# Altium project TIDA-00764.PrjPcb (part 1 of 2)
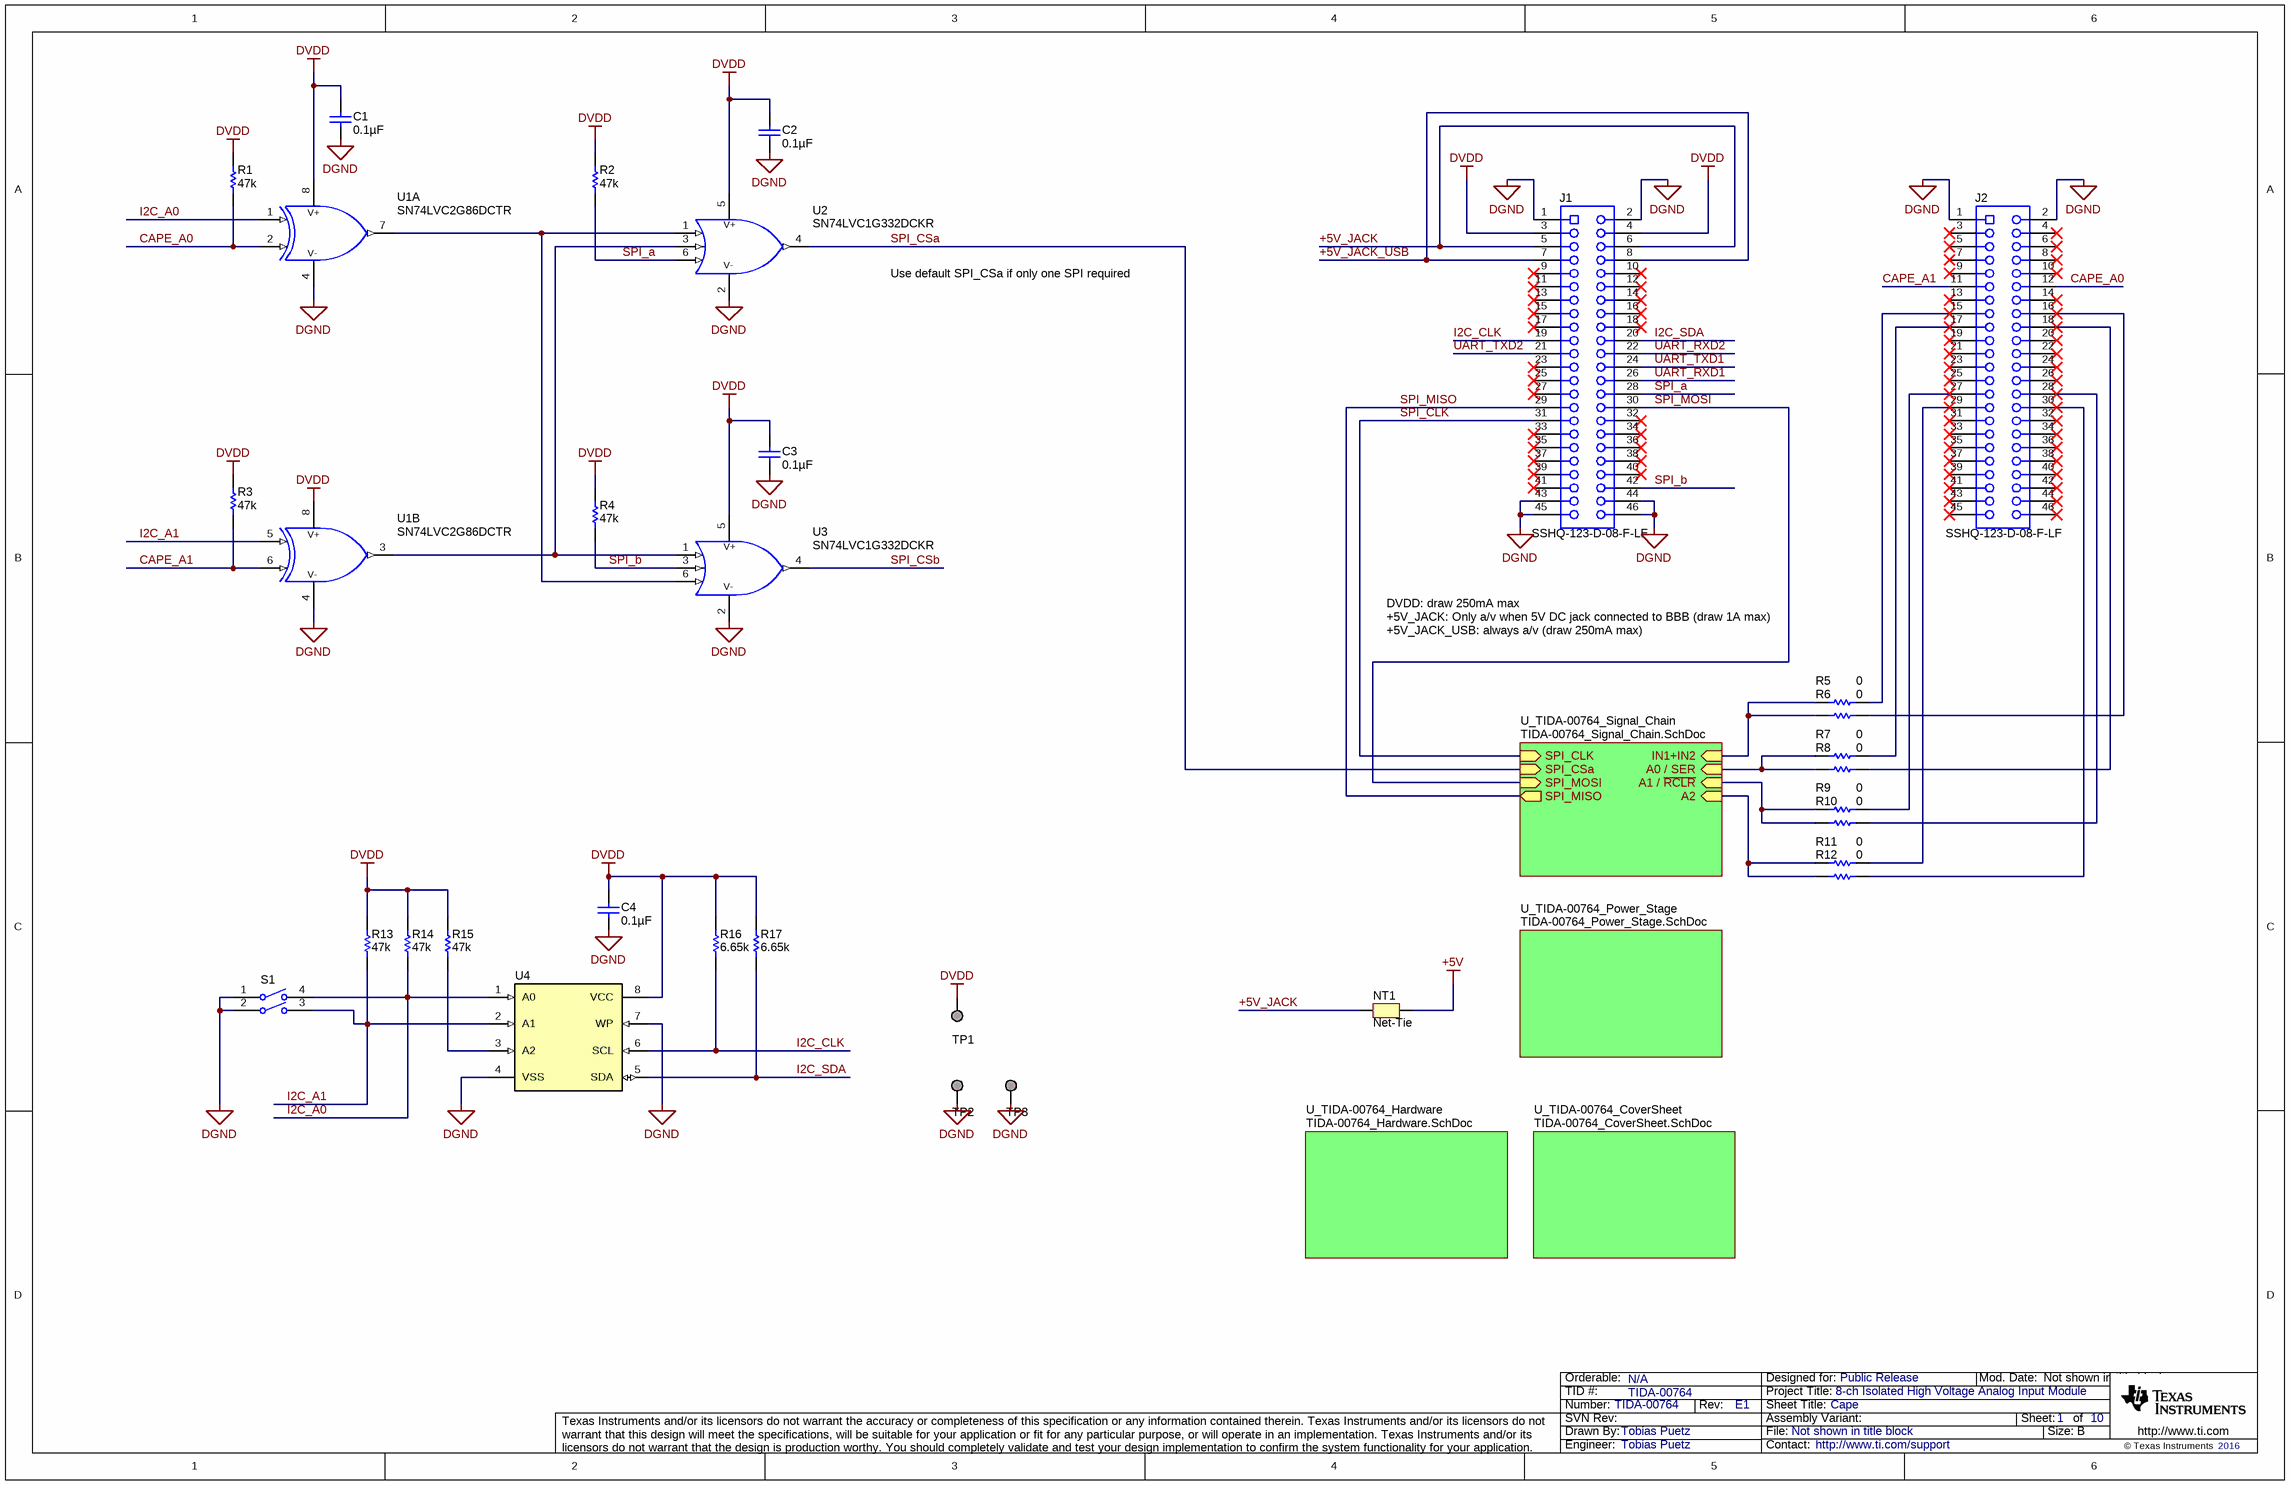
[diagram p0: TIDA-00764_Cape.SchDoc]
CopyrightYear: 2016; EVM_Orderable: N/A; PCB_Layout: Tobias Puetz; PCB_Rev: E1; PRJ_Customer: Public Release; PRJ_Engineer: Tobias Puetz; PRJ_Number: TIDA-00764; PRJ_Title: 8-ch Isolated High Voltage Analog Input Module; SCH_Rev: E1; TechSupport: http://www.ti.com/support; TID: TIDA-00764
10 sheets, 232 parts. Net scope: hierarchical (ports join the sheet entries above them; power ports are global).
Board file: TIDA-00764.PcbDoc
Sheets:
  TIDA-00764_Cape.SchDoc
    U_TIDA-00764_CoverSheet = TIDA-00764_CoverSheet.SchDoc
    U_TIDA-00764_Hardware = TIDA-00764_Hardware.SchDoc
    U_TIDA-00764_Signal_Chain = TIDA-00764_Signal_Chain.SchDoc
      Channel_Inputs = TIDA-00764_Channel_Inputs.SchDoc
        CMCh1 = TIDA-00764_CMCh_Input.SchDoc
        CMCh3 = TIDA-00764_CMCh_Input.SchDoc
        CMCh2 = TIDA-00764_CMCh_Input.SchDoc
        CMCh4 = TIDA-00764_CMCh_Input.SchDoc
        NoCMCh1 = TIDA-00764_Ch_Input.SchDoc
        NoCMCh2 = TIDA-00764_Ch_Input.SchDoc
        NoCMCh3 = TIDA-00764_Ch_Input.SchDoc
        NoCMCh4 = TIDA-00764_Ch_Input.SchDoc
      MUX_Stage = TIDA-00764_MUX_Stage.SchDoc
      Digital_Isolation = TIDA-00764_Digital_Isolation.SchDoc
    U_TIDA-00764_Power_Stage = TIDA-00764_Power_Stage.SchDoc

## Sheet TIDA-00764_Cape.SchDoc: Cape
size 431 x 279 mm; Date: Not shown in title block; ApprovedBy: Not shown in title block; CheckedBy: Not shown in title block; Author: Not shown in title block; CompanyName: Not shown in title block; DrawnBy: Tobias Puetz; Engineer: Not shown in title block; Organization: Not shown in title block; Address1: Not shown in title block; Address2: Not shown in title block; Address3: Not shown in title block; Address4: Not shown in title block; DocumentNumber: 1; Revision: Use project parameter SCH_Rev; SheetNumber: 1; SheetTotal: 10; PageSetup: Record=PageOptions¦CenterHorizontal=True¦CenterVertical=True¦PrintScale=0.62¦XCorrection=1.00¦YCorrection=1.00¦PrintKind=0¦BorderSize=5000000¦LeftOffset=0¦BottomOffset=0¦Orientation=2¦PaperLength=1000¦PaperWidth=1000¦Scale=100¦PaperSource=15¦PrintQuality=600¦MediaType=1¦DitherType=10¦PrintScaleMode=1¦PaperKind=Letter

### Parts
C1  ValueDisplayed: 0.1µF  [0402]  (hidden comment: C1005X7R1H104K050BB)
C2  ValueDisplayed: 0.1µF  [0402]  (hidden comment: C1005X7R1H104K050BB)
C3  ValueDisplayed: 0.1µF  [0402]  (hidden comment: C1005X7R1H104K050BB)
C4  ValueDisplayed: 0.1µF  [0402]  (hidden comment: C1005X7R1H104K050BB)
J1  SSHQ-123-D-08-F-LF  [Major_BBB_SSHQ-123-D-08]
J2  SSHQ-123-D-08-F-LF  [Major_BBB_SSHQ-123-D-08]
NT1  Net-Tie  [Net-Tie_20milWide_60milLong]  (net tie, no BOM)
R1  ValueDisplayed: 47k  [0402]  (hidden comment: CRCW040247K0JNED)
R2  ValueDisplayed: 47k  [0402]  (hidden comment: CRCW040247K0JNED)
R3  ValueDisplayed: 47k  [0402]  (hidden comment: CRCW040247K0JNED)
R4  ValueDisplayed: 47k  [0402]  (hidden comment: CRCW040247K0JNED)
R5  ValueDisplayed: 0  [0603]  (hidden comment: CRCW06030000Z0EA)
R6  ValueDisplayed: 0  [0603]  (hidden comment: CRCW06030000Z0EA)
R7  ValueDisplayed: 0  [0603]  (hidden comment: CRCW06030000Z0EA)
R8  ValueDisplayed: 0  [0603]  (hidden comment: CRCW06030000Z0EA)
R9  ValueDisplayed: 0  [0603]  (hidden comment: CRCW06030000Z0EA)
R10  ValueDisplayed: 0  [0603]  (hidden comment: CRCW06030000Z0EA)
R11  ValueDisplayed: 0  [0603]  (hidden comment: CRCW06030000Z0EA)
R12  ValueDisplayed: 0  [0603]  (hidden comment: CRCW06030000Z0EA)
R13  ValueDisplayed: 47k  [0402]  (hidden comment: CRCW040247K0JNED)
R14  ValueDisplayed: 47k  [0402]  (hidden comment: CRCW040247K0JNED)
R15  ValueDisplayed: 47k  [0402]  (hidden comment: CRCW040247K0JNED)
R16  ValueDisplayed: 6.65k  [0402]  (hidden comment: CRCW04026K65FKED)
R17  ValueDisplayed: 6.65k  [0402]  (hidden comment: CRCW04026K65FKED)
S1  416131160802  [SW_416131160802]  (value not drawn)
TP1  TESTPOINT  [TESTPOINT]  (value not drawn)  (no BOM)
TP2  TESTPOINT  [TESTPOINT]  (value not drawn)  (no BOM)
TP3  TESTPOINT  [TESTPOINT]  (value not drawn)  (no BOM)
U1  SN74LVC2G86DCTR  [DCT0008A_N]  (parts A,B of 2)
U2  SN74LVC1G332DCKR  [DCK0006A_N]
U3  SN74LVC1G332DCKR  [DCK0006A_N]
U4  24LC256-I/ST  [TSSOP-8]  (value not drawn)

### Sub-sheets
U_TIDA-00764_CoverSheet = TIDA-00764_CoverSheet.SchDoc: no entries
U_TIDA-00764_Hardware = TIDA-00764_Hardware.SchDoc: no entries
U_TIDA-00764_Power_Stage = TIDA-00764_Power_Stage.SchDoc: no entries
U_TIDA-00764_Signal_Chain = TIDA-00764_Signal_Chain.SchDoc: SPI_CSa (in), SPI_CLK (in), SPI_MISO (out), SPI_MOSI (in), A2 (in), A1 / ~{RCLR} (in), A0 / SER (in), IN1+IN2 (in)

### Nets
+5V: NT1.2
DGND: C1.2 C2.2 C3.2 C4.2 J1.1 J1.2 J1.43 J1.44 J1.45 J1.46 J2.1 J2.2 S1.1 S1.2 TP2.1 TP3.1 U1.4(GND) U2.2(GND) U3.2(GND) U4.4(VSS) U4.7(WP)
DVDD: C1.1 C2.1 C3.1 C4.1 J1.3 J1.4 R1.1 R2.1 R3.1 R4.1 R13.1 R14.1 R15.1 R16.1 R17.1 TP1.1 U1.8(VCC) U2.5(VCC) U3.5(VCC) U4.8(VCC)
+5V_JACK: J1.5 J1.6 NT1.1
+5V_JACK_USB: J1.7 J1.8
A0 / SER: R7.2 R8.2 ; sheet U_TIDA-00764_Signal_Chain/A0 / SER
A1 / ~{RCLR}: R9.2 R10.2 ; sheet U_TIDA-00764_Signal_Chain/A1 / ~{RCLR}
A2: R11.2 R12.2 ; sheet U_TIDA-00764_Signal_Chain/A2
CAPE_A0: J2.12 R1.2 U1.2(1B)
CAPE_A1: J2.11 R3.2 U1.6(2B)
I2C_A0: R14.2 S1.4 U1.1(1A) U4.1(A0)
I2C_A1: R13.2 S1.3 U1.5(2A) U4.2(A1)
I2C_CLK: J1.19 R16.2 U4.6(SCL)
I2C_SDA: J1.20 R17.2 U4.5(SDA)
IN1+IN2: R5.2 R6.2 ; sheet U_TIDA-00764_Signal_Chain/IN1+IN2
SPI_a: J1.28 R2.2 U2.6(C)
SPI_b: J1.42 R4.2 U3.3(B)
SPI_CLK: J1.31 ; sheet U_TIDA-00764_Signal_Chain/SPI_CLK
SPI_CSa: U2.4(Y) ; sheet U_TIDA-00764_Signal_Chain/SPI_CSa
SPI_CSb: U3.4(Y)
SPI_MISO: J1.29 ; sheet U_TIDA-00764_Signal_Chain/SPI_MISO
SPI_MOSI: J1.30 ; sheet U_TIDA-00764_Signal_Chain/SPI_MOSI
UART_RXD1: J1.26
UART_RXD2: J1.22
UART_TXD1: J1.24
UART_TXD2: J1.21
NetJ2_15: J2.15 R5.1
NetJ2_16: J2.16 R6.1
NetJ2_17: J2.17 R7.1
NetJ2_18: J2.18 R8.1
NetJ2_27: J2.27 R9.1
NetJ2_28: J2.28 R10.1
NetJ2_29: J2.29 R11.1
NetJ2_30: J2.30 R12.1
NetR15_2: R15.2 U4.3(A2)
NetU1_3: U1.3(2Y) U2.3(B) U3.1(A)
NetU1_7: U1.7(1Y) U2.1(A) U3.6(C)

Not connected (* = marked no-connect by the designer): J1 9* 10* 11* 12* 13* 14* 15* 16* 17* 18* 23* 25* 27* 32* 33* 34* 35* 36* 37* 38* 39* 40* 41*; J2 3* 4* 5* 6* 7* 8* 9* 10* 13* 14* 19* 20* 21* 22* 23* 24* 25* 26* 31* 32* 33* 34* 35* 36* 37* 38* 39* 40* 41* 42* 43* 44* 45* 46*

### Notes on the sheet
- Use default SPI_CSa if only one SPI required
- DVDD: draw 250mA max
  +5V_JACK: Only a/v when 5V DC jack connected to BBB (draw 1A max)
  +5V_JACK_USB: always a/v (draw 250mA max)

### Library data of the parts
C1-C4 = C1005X7R1H104K050BB: CAP, CERM, 0.1 µF, 50 V, +/- 10%, X7R, 0402; Manufacturer: TDK; Polarized: N; CompType: Capacitor; Value: 0.1uF; U/M: EA; Cap_F: 0.0000001; Tolerance_%: 10; ESR_ohm: 0.039064; Value1: 0.039064 ohm; VDC_V: 50; Value2: 50V; IRMS_A: 0.814669; TaMin_C: -55; TaMax_C: 125; AEC Category: Q200
J1 J2 = SSHQ-123-D-08-F-LF: Female Connector, 2.54mm, 23x2, TH; Manufacturer: Major League Electronics; SymbolCreator: Altium; CompType: Receptacle
NT1 = Net-Tie: Single point connection between nets.; SymbolCreator: codlsc
R1-R4 R13-R15 = CRCW040247K0JNED: RES, 47 k, 5%, 0.063 W, 0402; Manufacturer: Vishay-Dale; CompType: Resistor; Value: 47k; Res_ohm: 47000; Value_Code: 47k0; Tolerance_%: 5; Power_W: 0.063; Value2: 0.063W; VDC_V: 50; TempCo: 200 ppm/C; EIA_Code: E24; U/M: EA; AEC Category: Q200
R5-R12 = CRCW06030000Z0EA: RES, 0, 5%, 0.1 W, 0603; Manufacturer: Vishay-Dale; CompType: Resistor; Value: 0; Value_Code: 0000; Tolerance_%: 5; Power_W: 0.1; Value2: 0.1W; VDC_V: 75; TempCo: 200 ppm/C; EIA_Code: E24; U/M: EA; AEC Category: Q200
R16 R17 = CRCW04026K65FKED: RES, 6.65 k, 1%, 0.063 W, 0402; Manufacturer: Vishay-Dale; CompType: Resistor; Value: 6.65k; Res_ohm: 6650; Value_Code: 6k65; Tolerance_%: 1; Power_W: 0.063; Value2: 0.063W; VDC_V: 50; TempCo: 100 ppm/C; EIA_Code: E96; U/M: EA; AEC Category: Q200
S1 = 416131160802: Switch, SPST, Off-On, 2 Pos, SMD; Manufacturer: Wurth Elektronik; SymbolCreator: Altium; VDC_V: 24; PositionCount: 2; CurrentRating_mA: 25
TP1-TP3 = TESTPOINT: TEST POINT.  No entry in BOM.
U1 = SN74LVC2G86DCTR: Dual 2-Input Exclusive-OR Gate, DCT0008A; Manufacturer: Texas Instruments; SymbolCreator: a0411947; CompType: IC; U/M: EA
U2 U3 = SN74LVC1G332DCKR: Single 3-Input Positive-OR Gate, DCK0006A; Manufacturer: Texas Instruments; SymbolCreator: Altium; CompType: IC; U/M: EA
U4 = 24LC256-I/ST: 256K I2C CMOS Serial EEPROM, TSSOP-8; Manufacturer: Microchip; SymbolCreator: a0411947

## Sheet TIDA-00764_CoverSheet.SchDoc: Block Diagram
size 431 x 279 mm; Date: Not shown in title block; ApprovedBy: Not shown in title block; CheckedBy: Not shown in title block; Author: Not shown in title block; CompanyName: Not shown in title block; DrawnBy: Tobias Puetz; Engineer: Not shown in title block; Organization: Not shown in title block; Address1: Not shown in title block; Address2: Not shown in title block; Address3: Not shown in title block; Address4: Not shown in title block; DocumentNumber: 2; Revision: Use project parameter SCH_Rev; SheetNumber: 2; SheetTotal: 10; PageSetup: Record=PageOptions¦CenterHorizontal=True¦CenterVertical=True¦PrintScale=1.00¦XCorrection=1.00¦YCorrection=1.00¦PrintKind=0¦BorderSize=5000000¦LeftOffset=0¦BottomOffset=0¦Orientation=2¦PaperLength=1000¦PaperWidth=1000¦Scale=100¦PaperSource=15¦PrintQuality=600¦MediaType=1¦DitherType=10¦PaperKind=Letter¦PrintScaleMode=1
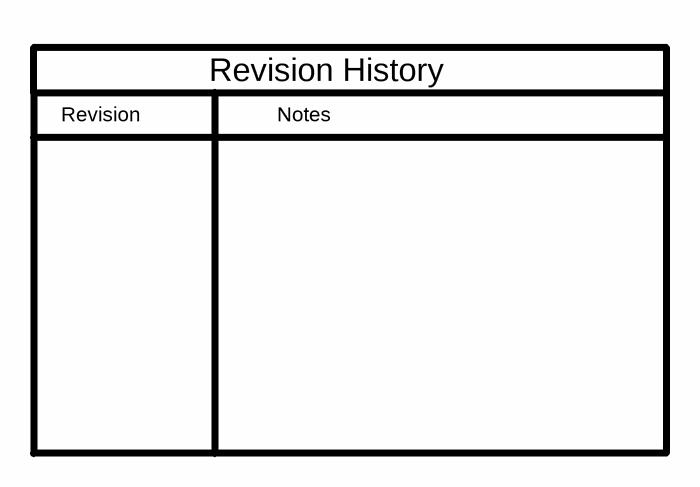
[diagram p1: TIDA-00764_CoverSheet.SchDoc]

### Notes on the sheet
- Revision
- Notes
- Revision History

## Sheet TIDA-00764_Hardware.SchDoc: Hardware
size 431 x 279 mm; Date: Not shown in title block; ApprovedBy: Not shown in title block; CheckedBy: Not shown in title block; Author: Not shown in title block; CompanyName: Not shown in title block; DrawnBy: Tobias Puetz; Engineer: Not shown in title block; Organization: Not shown in title block; Address1: Not shown in title block; Address2: Not shown in title block; Address3: Not shown in title block; Address4: Not shown in title block; DocumentNumber: 3; Revision: Use project parameter SCH_Rev; SheetNumber: 3; SheetTotal: 10; PageSetup: Record=PageOptions¦CenterHorizontal=True¦CenterVertical=True¦PrintScale=1.00¦XCorrection=1.00¦YCorrection=1.00¦PrintKind=0¦BorderSize=5000000¦LeftOffset=0¦BottomOffset=0¦Orientation=2¦PaperLength=1000¦PaperWidth=1000¦Scale=100¦PaperSource=15¦PrintQuality=600¦MediaType=1¦DitherType=10¦PaperKind=Letter¦PrintScaleMode=1
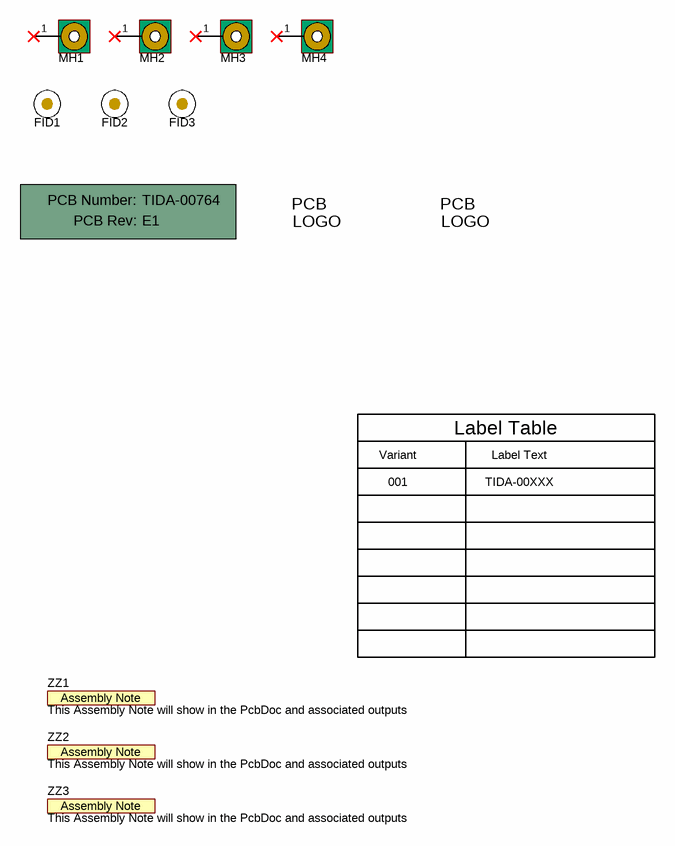
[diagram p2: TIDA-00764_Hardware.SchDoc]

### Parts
!PCB1  Printed Circuit Board  (value not drawn)  (mechanical)
FID1  Fiducial  [Fiducial10-20]  (value not drawn)
FID2  Fiducial  [Fiducial10-20]  (value not drawn)
FID3  Fiducial  [Fiducial10-20]  (value not drawn)
Logo1  Texas Instruments  [TI_Symbol_Overlay_Medium]  (value not drawn)  (no BOM)
Logo2  Pb-Free Symbol  [Pb-Free_Overlay_Small]  (value not drawn)  (no BOM)
MH1  MTG_Pads  [MTGP_4-40_PanHead]  (value not drawn)  (no BOM)
MH2  MTG_Pads  [MTGP_4-40_PanHead]  (value not drawn)  (no BOM)
MH3  MTG_Pads  [MTGP_4-40_PanHead]  (value not drawn)  (no BOM)
MH4  MTG_Pads  [MTGP_4-40_PanHead]  (value not drawn)  (no BOM)
ZZ1  This Assembly Note will show in the PcbDoc and associated outputs  [AssemblyNote]  (no BOM)
ZZ2  This Assembly Note will show in the PcbDoc and associated outputs  [AssemblyNote]  (no BOM)
ZZ3  This Assembly Note will show in the PcbDoc and associated outputs  [AssemblyNote]  (no BOM)

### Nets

Not connected (* = marked no-connect by the designer): MH1 1*; MH2 1*; MH3 1*; MH4 1*

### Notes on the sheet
- Variant
- Label Table
- Label Text
- 001
- TIDA-00XXX

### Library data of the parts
!PCB1 = PCB: Manufacturer: Any; PartNumber: TIDA-00764; SymbolCreator: a0412235
FID1-FID3 = Fiducial: Fiducial mark.  There is nothing to buy or mount.; SymbolCreator: codlsc
Logo1 = TI_Logo: Texas Instrument Corporate Signature; SymbolCreator: a0412235
Logo2 = Pb-Free: SymbolCreator: a0412235
MH1-MH4 = Mounting Hole (Imperial) with Pads: PCB Mounting Hole; Manufacturer: Any; SymbolCreator: a0412235
ZZ1-ZZ3 = AssemblyNote: SymbolCreator: codlsc

## Sheet TIDA-00764_Signal_Chain.SchDoc: Signal Chain
size 431 x 279 mm; Date: Not shown in title block; ApprovedBy: Not shown in title block; CheckedBy: Not shown in title block; Author: Not shown in title block; CompanyName: Not shown in title block; DrawnBy: Tobias Puetz; Engineer: Not shown in title block; Organization: Not shown in title block; Address1: Not shown in title block; Address2: Not shown in title block; Address3: Not shown in title block; Address4: Not shown in title block; DocumentNumber: 5; Revision: Use project parameter SCH_Rev; SheetNumber: 5; SheetTotal: 10; PageSetup: Record=PageOptions¦CenterHorizontal=True¦CenterVertical=True¦PrintScale=1.00¦XCorrection=1.00¦YCorrection=1.00¦PrintKind=0¦BorderSize=5000000¦LeftOffset=0¦BottomOffset=0¦Orientation=2¦PaperLength=1000¦PaperWidth=1000¦Scale=100¦PaperSource=15¦PrintQuality=600¦MediaType=1¦DitherType=10¦PaperKind=Letter¦PrintScaleMode=1
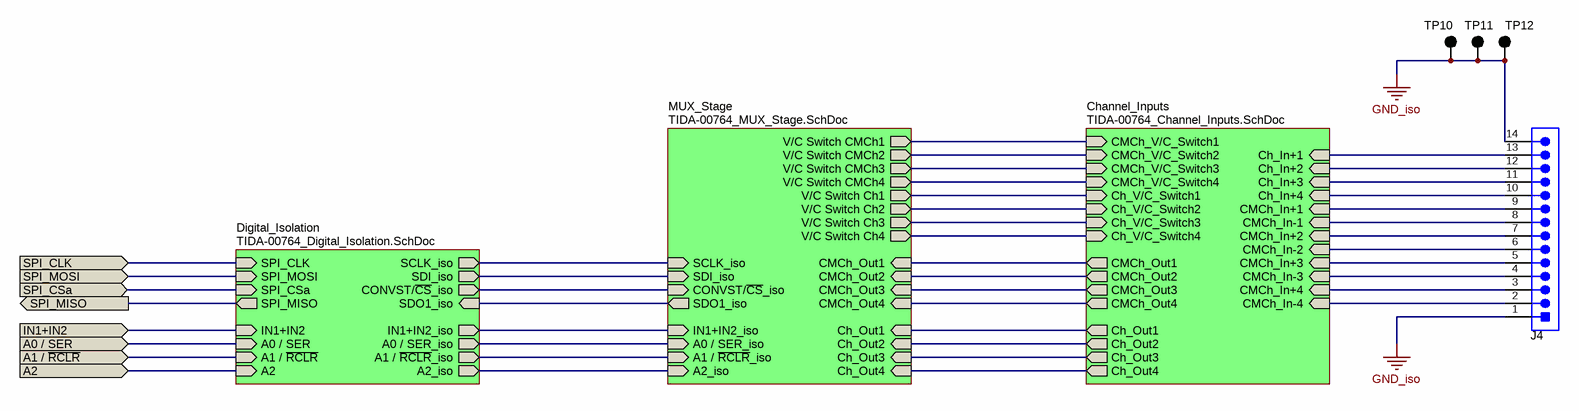
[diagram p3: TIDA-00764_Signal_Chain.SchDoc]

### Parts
J4  1844333  [Phoenix_1844333]  (value not drawn)
TP10  5001  [Keystone5001]  (value not drawn)
TP11  5001  [Keystone5001]  (value not drawn)
TP12  5001  [Keystone5001]  (value not drawn)

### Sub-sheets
Channel_Inputs = TIDA-00764_Channel_Inputs.SchDoc: Ch_Out1 (out), Ch_Out2 (out), Ch_Out4 (out), Ch_Out3 (out), CMCh_Out1 (out), CMCh_V/C_Switch1 (in), CMCh_V/C_Switch2 (in), CMCh_V/C_Switch3 (in), CMCh_V/C_Switch4 (in), Ch_V/C_Switch1 (in), Ch_V/C_Switch2 (in), Ch_V/C_Switch3 (in), Ch_V/C_Switch4 (in), CMCh_Out2 (out), CMCh_Out3 (out), CMCh_Out4 (out), CMCh_In+1 (in), CMCh_In+2 (in), CMCh_In+3 (in), CMCh_In+4 (in), CMCh_In-1 (in), CMCh_In-2 (in), CMCh_In-3 (in), CMCh_In-4 (in), Ch_In+1 (in), Ch_In+2 (in), Ch_In+3 (in), Ch_In+4 (in)
Digital_Isolation = TIDA-00764_Digital_Isolation.SchDoc: SPI_CLK (in), SPI_MOSI (in), SPI_MISO (out), A2 (in), A1 / ~{RCLR} (in), A0 / SER (in), IN1+IN2 (in), SPI_CSa (in), SCLK_iso (out), SDI_iso (out), SDO1_iso (in), CONVST/~{CS}_iso (out), A2_iso (out), A1 / ~{RCLR}_iso (out), A0 / SER_iso (out), IN1+IN2_iso (out)
MUX_Stage = TIDA-00764_MUX_Stage.SchDoc: V/C Switch CMCh1 (out), V/C Switch CMCh2 (out), V/C Switch CMCh3 (out), V/C Switch CMCh4 (out), V/C Switch Ch1 (out), V/C Switch Ch2 (out), V/C Switch Ch3 (out), V/C Switch Ch4 (out), CMCh_Out1 (in), CMCh_Out2 (in), CMCh_Out3 (in), CMCh_Out4 (in), Ch_Out1 (in), Ch_Out2 (in), Ch_Out3 (in), Ch_Out4 (in), SCLK_iso (in), SDI_iso (in), SDO1_iso (out), A2_iso (in), A0 / SER_iso (in), IN1+IN2_iso (in), CONVST/~{CS}_iso (in), A1 / ~{RCLR}_iso (in)

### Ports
A0 / SER (in), A1 / ~{RCLR} (in), A2 (in), IN1+IN2 (in), SPI_CLK (in), SPI_CSa (in), SPI_MISO (out), SPI_MOSI (in)

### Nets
GND_iso: J4.1 J4.14 TP10.1 TP11.1 TP12.1
A0 / SER: port A0 / SER, sheet Digital_Isolation/A0 / SER
A0 / SER_iso: sheet MUX_Stage/A0 / SER_iso, sheet Digital_Isolation/A0 / SER_iso
A1 / ~{RCLR}: port A1 / ~{RCLR}, sheet Digital_Isolation/A1 / ~{RCLR}
A1 / ~{RCLR}_iso: sheet MUX_Stage/A1 / ~{RCLR}_iso, sheet Digital_Isolation/A1 / ~{RCLR}_iso
A2: port A2, sheet Digital_Isolation/A2
A2_iso: sheet MUX_Stage/A2_iso, sheet Digital_Isolation/A2_iso
Ch_In+: J4.10 ; sheet Channel_Inputs/Ch_Out4, sheet Channel_Inputs/Ch_In+4, sheet MUX_Stage/Ch_Out4
Ch_In+: J4.11 ; sheet Channel_Inputs/Ch_Out3, sheet Channel_Inputs/Ch_In+3, sheet MUX_Stage/Ch_Out3  [a separate net that carries the same name]
Ch_In+: J4.12 ; sheet Channel_Inputs/Ch_Out2, sheet Channel_Inputs/Ch_In+2, sheet MUX_Stage/Ch_Out2  [a separate net that carries the same name]
Ch_In+: J4.13 ; sheet Channel_Inputs/Ch_Out1, sheet Channel_Inputs/Ch_In+1, sheet MUX_Stage/Ch_Out1  [a separate net that carries the same name]
Ch_V/C_Switch: sheet Channel_Inputs/Ch_V/C_Switch1, sheet MUX_Stage/V/C Switch Ch1
Ch_V/C_Switch: sheet Channel_Inputs/Ch_V/C_Switch2, sheet MUX_Stage/V/C Switch Ch2  [a separate net that carries the same name]
Ch_V/C_Switch: sheet Channel_Inputs/Ch_V/C_Switch3, sheet MUX_Stage/V/C Switch Ch3  [a separate net that carries the same name]
Ch_V/C_Switch: sheet Channel_Inputs/Ch_V/C_Switch4, sheet MUX_Stage/V/C Switch Ch4  [a separate net that carries the same name]
CMCh_In+: J4.5 ; sheet Channel_Inputs/CMCh_In+3
CMCh_In+: J4.3 ; sheet Channel_Inputs/CMCh_In+4  [a separate net that carries the same name]
CMCh_In+: J4.7 ; sheet Channel_Inputs/CMCh_In+2  [a separate net that carries the same name]
CMCh_In+: J4.9 ; sheet Channel_Inputs/CMCh_In+1  [a separate net that carries the same name]
CMCh_In-: J4.4 ; sheet Channel_Inputs/CMCh_In-3
CMCh_In-: J4.2 ; sheet Channel_Inputs/CMCh_In-4  [a separate net that carries the same name]
CMCh_In-: J4.6 ; sheet Channel_Inputs/CMCh_In-2  [a separate net that carries the same name]
CMCh_In-: J4.8 ; sheet Channel_Inputs/CMCh_In-1  [a separate net that carries the same name]
CMCh_Out: sheet Channel_Inputs/CMCh_Out1, sheet MUX_Stage/CMCh_Out1
CMCh_Out: sheet Channel_Inputs/CMCh_Out3, sheet MUX_Stage/CMCh_Out3  [a separate net that carries the same name]
CMCh_Out: sheet Channel_Inputs/CMCh_Out2, sheet MUX_Stage/CMCh_Out2  [a separate net that carries the same name]
CMCh_Out: sheet Channel_Inputs/CMCh_Out4, sheet MUX_Stage/CMCh_Out4  [a separate net that carries the same name]
CMCh_V/C_Switch: sheet Channel_Inputs/CMCh_V/C_Switch1, sheet MUX_Stage/V/C Switch CMCh1
CMCh_V/C_Switch: sheet Channel_Inputs/CMCh_V/C_Switch3, sheet MUX_Stage/V/C Switch CMCh3  [a separate net that carries the same name]
CMCh_V/C_Switch: sheet Channel_Inputs/CMCh_V/C_Switch2, sheet MUX_Stage/V/C Switch CMCh2  [a separate net that carries the same name]
CMCh_V/C_Switch: sheet Channel_Inputs/CMCh_V/C_Switch4, sheet MUX_Stage/V/C Switch CMCh4  [a separate net that carries the same name]
CONVST/~{CS}_iso: sheet MUX_Stage/CONVST/~{CS}_iso, sheet Digital_Isolation/CONVST/~{CS}_iso
IN1+IN2: port IN1+IN2, sheet Digital_Isolation/IN1+IN2
IN1+IN2_iso: sheet MUX_Stage/IN1+IN2_iso, sheet Digital_Isolation/IN1+IN2_iso
SCLK_iso: sheet MUX_Stage/SCLK_iso, sheet Digital_Isolation/SCLK_iso
SDI_iso: sheet MUX_Stage/SDI_iso, sheet Digital_Isolation/SDI_iso
SDO1_iso: sheet MUX_Stage/SDO1_iso, sheet Digital_Isolation/SDO1_iso
SPI_CLK: port SPI_CLK, sheet Digital_Isolation/SPI_CLK
SPI_CSa: port SPI_CSa, sheet Digital_Isolation/SPI_CSa
SPI_MISO: port SPI_MISO, sheet Digital_Isolation/SPI_MISO
SPI_MOSI: port SPI_MOSI, sheet Digital_Isolation/SPI_MOSI

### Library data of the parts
J4 = 1844333: Header (Shrouded), 3.5mm, 14x1, Tin, R/A, TH; Manufacturer: Phoenix Contact; SymbolCreator: a0411947; Pitch_mm: 3.5; Gender: Male; Shrouded: Y; Row_Count: 1; Current_A: 8; Voltage_V: 160
TP10-TP12 = 5001: Test Point, Miniature, Black, TH; Manufacturer: Keystone; CompType: Test Point Loop; ContactFinish: Silver

## Sheet TIDA-00764_Channel_Inputs.SchDoc: Channel Inputs
size 431 x 279 mm; Date: Not shown in title block; ApprovedBy: Not shown in title block; CheckedBy: Not shown in title block; Author: Not shown in title block; CompanyName: Not shown in title block; DrawnBy: Tobias Puetz; Engineer: Not shown in title block; Organization: Not shown in title block; Address1: Not shown in title block; Address2: Not shown in title block; Address3: Not shown in title block; Address4: Not shown in title block; DocumentNumber: 6; Revision: Use project parameter SCH_Rev; SheetNumber: 6; SheetTotal: 10; PageSetup: Record=PageOptions¦CenterHorizontal=True¦CenterVertical=True¦PrintScale=1.00¦XCorrection=1.00¦YCorrection=1.00¦PrintKind=0¦BorderSize=5000000¦LeftOffset=0¦BottomOffset=0¦Orientation=2¦PaperLength=1000¦PaperWidth=1000¦Scale=100¦PaperSource=15¦PrintQuality=600¦MediaType=1¦DitherType=10¦PaperKind=Letter¦PrintScaleMode=1
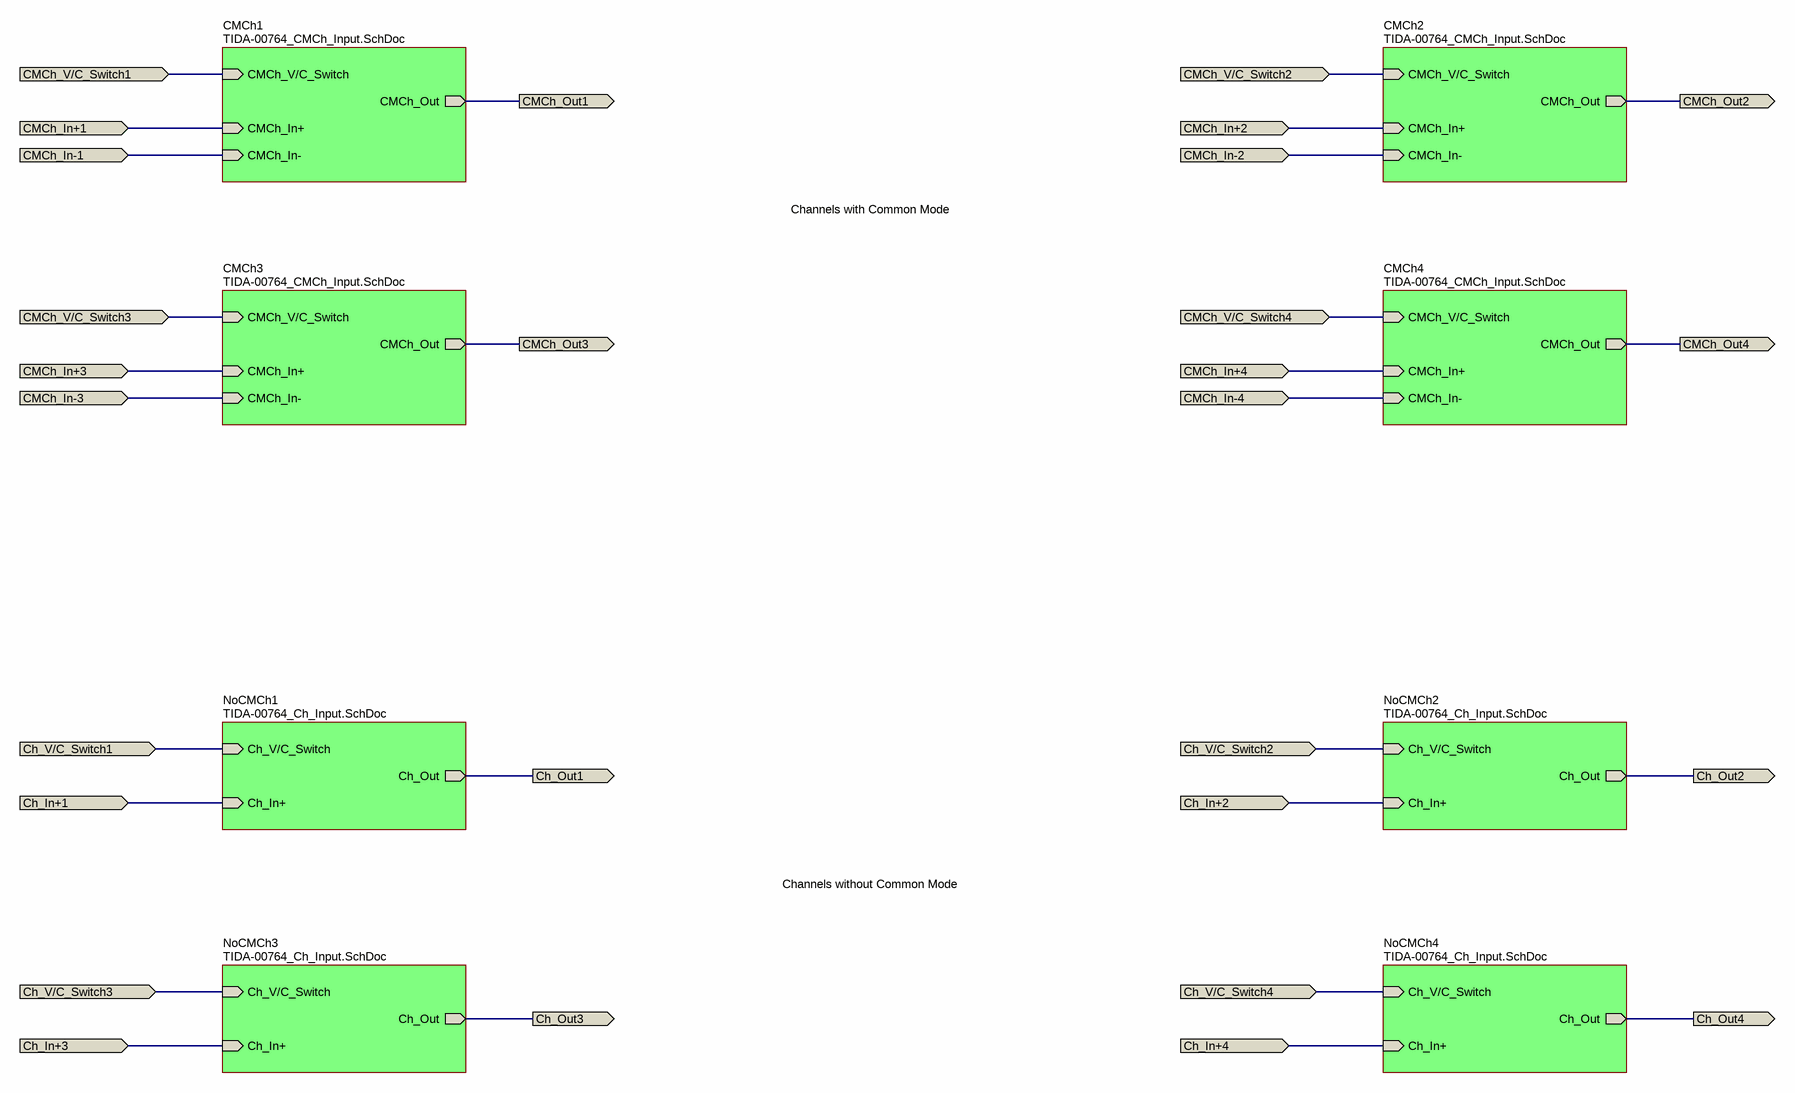
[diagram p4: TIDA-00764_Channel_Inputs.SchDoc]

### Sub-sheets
CMCh1 = TIDA-00764_CMCh_Input.SchDoc: CMCh_V/C_Switch (in), CMCh_Out (out), CMCh_In+ (in), CMCh_In- (in)
CMCh2 = TIDA-00764_CMCh_Input.SchDoc: CMCh_V/C_Switch (in), CMCh_Out (out), CMCh_In+ (in), CMCh_In- (in)
CMCh3 = TIDA-00764_CMCh_Input.SchDoc: CMCh_V/C_Switch (in), CMCh_Out (out), CMCh_In+ (in), CMCh_In- (in)
CMCh4 = TIDA-00764_CMCh_Input.SchDoc: CMCh_V/C_Switch (in), CMCh_Out (out), CMCh_In+ (in), CMCh_In- (in)
NoCMCh1 = TIDA-00764_Ch_Input.SchDoc: Ch_V/C_Switch (in), Ch_Out (out), Ch_In+ (in)
NoCMCh2 = TIDA-00764_Ch_Input.SchDoc: Ch_V/C_Switch (in), Ch_Out (out), Ch_In+ (in)
NoCMCh3 = TIDA-00764_Ch_Input.SchDoc: Ch_V/C_Switch (in), Ch_Out (out), Ch_In+ (in)
NoCMCh4 = TIDA-00764_Ch_Input.SchDoc: Ch_V/C_Switch (in), Ch_Out (out), Ch_In+ (in)

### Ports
Ch_In+1 (in), Ch_In+2 (in), Ch_In+3 (in), Ch_In+4 (in), Ch_Out1 (out), Ch_Out2 (out), Ch_Out3 (out), Ch_Out4 (out), Ch_V/C_Switch1 (in), Ch_V/C_Switch2 (in), Ch_V/C_Switch3 (in), Ch_V/C_Switch4 (in), CMCh_In+1 (in), CMCh_In+2 (in), CMCh_In+3 (in), CMCh_In+4 (in), CMCh_In-1 (in), CMCh_In-2 (in), CMCh_In-3 (in), CMCh_In-4 (in), CMCh_Out1 (out), CMCh_Out2 (out), CMCh_Out3 (out), CMCh_Out4 (out), CMCh_V/C_Switch1 (in), CMCh_V/C_Switch2 (in), CMCh_V/C_Switch3 (in), CMCh_V/C_Switch4 (in)

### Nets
Ch_In+: port Ch_Out4, port Ch_In+4, sheet NoCMCh4/Ch_Out, sheet NoCMCh4/Ch_In+
Ch_In+: port Ch_Out3, port Ch_In+3, sheet NoCMCh3/Ch_Out, sheet NoCMCh3/Ch_In+  [a separate net that carries the same name]
Ch_In+: port Ch_Out2, port Ch_In+2, sheet NoCMCh2/Ch_Out, sheet NoCMCh2/Ch_In+  [a separate net that carries the same name]
Ch_In+: port Ch_Out1, port Ch_In+1, sheet NoCMCh1/Ch_Out, sheet NoCMCh1/Ch_In+  [a separate net that carries the same name]
Ch_V/C_Switch: port Ch_V/C_Switch1, sheet NoCMCh1/Ch_V/C_Switch
Ch_V/C_Switch: port Ch_V/C_Switch2, sheet NoCMCh2/Ch_V/C_Switch  [a separate net that carries the same name]
Ch_V/C_Switch: port Ch_V/C_Switch3, sheet NoCMCh3/Ch_V/C_Switch  [a separate net that carries the same name]
Ch_V/C_Switch: port Ch_V/C_Switch4, sheet NoCMCh4/Ch_V/C_Switch  [a separate net that carries the same name]
CMCh_In+: port CMCh_In+3, sheet CMCh3/CMCh_In+
CMCh_In+: port CMCh_In+4, sheet CMCh4/CMCh_In+  [a separate net that carries the same name]
CMCh_In+: port CMCh_In+2, sheet CMCh2/CMCh_In+  [a separate net that carries the same name]
CMCh_In+: port CMCh_In+1, sheet CMCh1/CMCh_In+  [a separate net that carries the same name]
CMCh_In-: port CMCh_In-3, sheet CMCh3/CMCh_In-
CMCh_In-: port CMCh_In-4, sheet CMCh4/CMCh_In-  [a separate net that carries the same name]
CMCh_In-: port CMCh_In-2, sheet CMCh2/CMCh_In-  [a separate net that carries the same name]
CMCh_In-: port CMCh_In-1, sheet CMCh1/CMCh_In-  [a separate net that carries the same name]
CMCh_Out: port CMCh_Out1, sheet CMCh1/CMCh_Out
CMCh_Out: port CMCh_Out3, sheet CMCh3/CMCh_Out  [a separate net that carries the same name]
CMCh_Out: port CMCh_Out2, sheet CMCh2/CMCh_Out  [a separate net that carries the same name]
CMCh_Out: port CMCh_Out4, sheet CMCh4/CMCh_Out  [a separate net that carries the same name]
CMCh_V/C_Switch: port CMCh_V/C_Switch1, sheet CMCh1/CMCh_V/C_Switch
CMCh_V/C_Switch: port CMCh_V/C_Switch3, sheet CMCh3/CMCh_V/C_Switch  [a separate net that carries the same name]
CMCh_V/C_Switch: port CMCh_V/C_Switch2, sheet CMCh2/CMCh_V/C_Switch  [a separate net that carries the same name]
CMCh_V/C_Switch: port CMCh_V/C_Switch4, sheet CMCh4/CMCh_V/C_Switch  [a separate net that carries the same name]

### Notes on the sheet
- Channels with Common Mode
- Channels without Common Mode

## Sheet TIDA-00764_CMCh_Input.SchDoc: CM Ch Input
size 431 x 279 mm; Date: Not shown in title block; ApprovedBy: Not shown in title block; CheckedBy: Not shown in title block; Author: Not shown in title block; CompanyName: Not shown in title block; DrawnBy: Tobias Puetz; Engineer: Not shown in title block; Organization: Not shown in title block; Address1: Not shown in title block; Address2: Not shown in title block; Address3: Not shown in title block; Address4: Not shown in title block; DocumentNumber: 7; Revision: Use project parameter SCH_Rev; SheetNumber: 7; SheetTotal: 10; PageSetup: Record=PageOptions¦CenterHorizontal=True¦CenterVertical=True¦PrintScale=1.00¦XCorrection=1.00¦YCorrection=1.00¦PrintKind=0¦BorderSize=5000000¦LeftOffset=0¦BottomOffset=0¦Orientation=2¦PaperLength=1000¦PaperWidth=1000¦Scale=100¦PaperSource=15¦PrintQuality=600¦MediaType=1¦DitherType=10¦PaperKind=Letter¦PrintScaleMode=1
Used 4 times, as channels U_TIDA-00764_Signal_Chain/Channel_Inputs/CMCh1, U_TIDA-00764_Signal_Chain/Channel_Inputs/CMCh3, U_TIDA-00764_Signal_Chain/Channel_Inputs/CMCh2, U_TIDA-00764_Signal_Chain/Channel_Inputs/CMCh4. Parts and nets are listed once, with the designators drawn on the sheet.
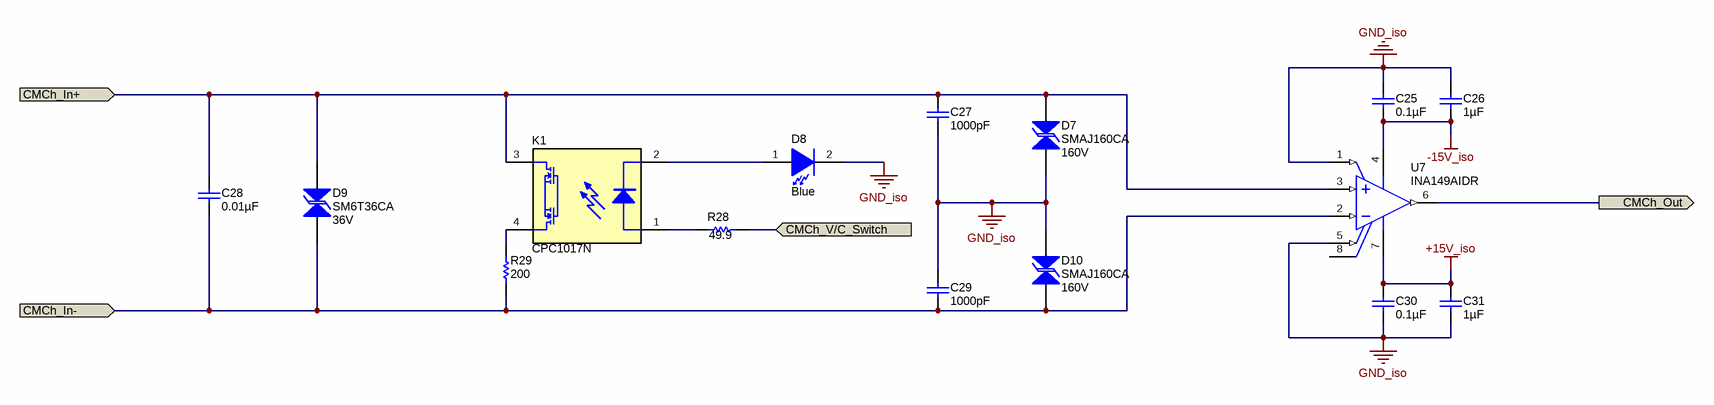
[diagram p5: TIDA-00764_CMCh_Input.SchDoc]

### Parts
C25  ValueDisplayed: 0.1µF  [0603]  (hidden comment: C1608X7R1H104K)
C26  ValueDisplayed: 1µF  [0603]  (hidden comment: C1608X7R1C105K080AC)
C27  ValueDisplayed: 1000pF  [0805_HV]  (hidden comment: C0805C102JBRACTU)
C28  ValueDisplayed: 0.01µF  [0603]  (hidden comment: C1608X7R2A103K)
C29  ValueDisplayed: 1000pF  [0805_HV]  (hidden comment: C0805C102JBRACTU)
C30  ValueDisplayed: 0.1µF  [0603]  (hidden comment: C1608X7R1H104K)
C31  ValueDisplayed: 1µF  [0603]  (hidden comment: C1608X7R1C105K080AC)
D7  SMAJ160CA  value 160V  [SMA]
D8  value Blue  [LB Q39G_BLUE]  (hidden comment: LB Q39G-L2N2-35-1)
D9  SM6T36CA  value 36V  [SMB-Bi]
D10  SMAJ160CA  value 160V  [SMA]
K1  CPC1017N  [RELAY_CPC1017N]
R28  ValueDisplayed: 49.9  [0603]  (hidden comment: CRCW060349R9FKEA)
R29  ValueDisplayed: 200  [0805_HV]  (hidden comment: RG2012P-201-B-T5)
U7  INA149AIDR  [D0008A_N]

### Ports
CMCh_In+ (in), CMCh_In- (in), CMCh_Out (out), CMCh_V/C_Switch (in)

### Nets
+15V_iso: C30.2 C31.1 U7.7(V+)
-15V_iso: C25.1 C26.2 U7.4(V-)
GND_iso: C25.2 C26.1 C27.2 C29.1 C30.1 C31.2 D7.2 D8.2(K) D10.2 U7.1(REFB) U7.5(REFA)
CMCh_In+: C27.1 C28.1 D7.1 D9.2 K1.3(LOAD) U7.3(IN+) ; port CMCh_In+
CMCh_In-: C28.2 C29.2 D9.1 D10.1 R29.1 U7.2(IN-) ; port CMCh_In-
CMCh_Out: U7.6(VOUT) ; port CMCh_Out
CMCh_V/C_Switch: R28.2 ; port CMCh_V/C_Switch
NetD8_1: D8.1(A) K1.2(CONTROL)
NetK1_1: K1.1(CONTROL+) R28.1
NetK1_4: K1.4(LOAD) R29.2

Not connected (* = marked no-connect by the designer): U7 8(NC)

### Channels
U_TIDA-00764_Signal_Chain/Channel_Inputs/CMCh1: designators end in _CMCh1; ports CMCh_In+=CMCh_In+ CMCh_In-=CMCh_In- CMCh_Out=CMCh_Out CMCh_V/C_Switch=CMCh_V/C_Switch
U_TIDA-00764_Signal_Chain/Channel_Inputs/CMCh3: designators end in _CMCh3; ports CMCh_In+=CMCh_In+ CMCh_In-=CMCh_In- CMCh_Out=CMCh_Out CMCh_V/C_Switch=CMCh_V/C_Switch
U_TIDA-00764_Signal_Chain/Channel_Inputs/CMCh2: designators end in _CMCh2; ports CMCh_In+=CMCh_In+ CMCh_In-=CMCh_In- CMCh_Out=CMCh_Out CMCh_V/C_Switch=CMCh_V/C_Switch
U_TIDA-00764_Signal_Chain/Channel_Inputs/CMCh4: designators end in _CMCh4; ports CMCh_In+=CMCh_In+ CMCh_In-=CMCh_In- CMCh_Out=CMCh_Out CMCh_V/C_Switch=CMCh_V/C_Switch

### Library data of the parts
C25 C30 = C1608X7R1H104K: CAP, CERM, 0.1 µF, 50 V, +/- 10%, X7R, 0603; Manufacturer: TDK; Polarized: N; CompType: Capacitor; Value: 0.1uF; U/M: EA; Cap_F: 0.0000001; Tolerance_%: 10; ESR_ohm: 0.017; Value1: 0.017 ohm; VDC_V: 50; Value2: 50V; TaMin_C: -55; TaMax_C: 125; AEC Category: Q200
C26 C31 = C1608X7R1C105K080AC: CAP, CERM, 1 µF, 16 V, +/- 10%, X7R, 0603; Manufacturer: TDK; Polarized: N; CompType: Capacitor; Value: 1uF; U/M: EA; Cap_F: 0.000001; Tolerance_%: 10; ESR_ohm: 0.0057; Value1: 0.0057 ohm; VDC_V: 16; Value2: 16V; TaMin_C: -55; TaMax_C: 125; AEC Category: Q200
C27 C29 = C0805C102JBRACTU: CAP, CERM, 1000 pF, 630 V, +/- 5%, X7R, 0805; Manufacturer: Kemet; Polarized: N; CompType: Capacitor; Value: 1000pF; U/M: EA; Cap_F: 0.000000001; Tolerance_%: 5; Value1: Unknown; VDC_V: 630; Value2: 630V; TaMin_C: -55; TaMax_C: 125; Cap_Case: 0805; AEC Category: Q200
C28 = C1608X7R2A103K: CAP, CERM, 0.01 µF, 100 V, +/- 10%, X7R, 0603; Manufacturer: TDK; Polarized: N; CompType: Capacitor; Value: 0.01uF; U/M: EA; Cap_F: 0.00000001; Tolerance_%: 10; ESR_ohm: 0.0661; Value1: 0.0661 ohm; VDC_V: 100; Value2: 100V; TaMin_C: -55; TaMax_C: 125; AEC Category: Q200
D7 D10 = SMAJ160CA: Diode, TVS, Bi, 160 V, 400 W, SMA; Manufacturer: Littelfuse; U/M: EA; Power_W: 400; Vr_V: 160; Value1: 400W; RJA_CperW: 120; AEC Category: Q101
D8 = LB Q39G-L2N2-35-1: LED, Blue, SMD; Manufacturer: OSRAM; Vf_V: 2.85; Value2: 2.85V; Io_A: 0.15; Tjmax_C: 95; Value1: W; U/M: EA
D9 = SM6T36CA: Diode, TVS, Bi, 36 V, 600 W, SMB; Manufacturer: STMicroelectronics; U/M: EA; Power_W: 600; Vr_V: 36; Value1: 600W; RJA_CperW: 100; AEC Category: Q101; AEC Qualified: N
K1 = CPC1017N: Relay, SPST-NO (1 Form A), 0.1 A, 1.2 VDC, SMD; Manufacturer: IXYS; SymbolCreator: Altium; Coil Voltage: 1.2 VDC; Contact Rating: 0.1 A; Time Operate (s): 0.01
R28 = CRCW060349R9FKEA: RES, 49.9, 1%, 0.1 W, 0603; Manufacturer: Vishay-Dale; CompType: Resistor; Value: 49.9; Value_Code: 49R9; Tolerance_%: 1; Power_W: 0.1; Value2: 0.1W; VDC_V: 75; TempCo: 100 ppm/C; EIA_Code: E96; U/M: EA; AEC Category: Q200
R29 = RG2012P-201-B-T5: RES, 200, 0.1%, 0.125 W, 0805; Manufacturer: Susumu Co Ltd; CompType: Resistor; Value: 200; Value_Code: 200R; Tolerance_%: 0.1; Power_W: 0.125; Value2: 0.125W; VDC_V: 100; TempCo: 25 ppm/C; EIA_Code: E192; U/M: EA; AEC Category: Q200
U7 = INA149AIDR: High Common-Mode Voltage Difference Amplifier, D0008A; Manufacturer: Texas Instruments; SymbolCreator: Altium; CompType: IC; U/M: EA

## Sheet TIDA-00764_Ch_Input.SchDoc: NoCM Ch Input
size 431 x 279 mm; Date: Not shown in title block; ApprovedBy: Not shown in title block; CheckedBy: Not shown in title block; Author: Not shown in title block; CompanyName: Not shown in title block; DrawnBy: Tobias Puetz; Engineer: Not shown in title block; Organization: Not shown in title block; Address1: Not shown in title block; Address2: Not shown in title block; Address3: Not shown in title block; Address4: Not shown in title block; DocumentNumber: 8; Revision: Use project parameter SCH_Rev; SheetNumber: 8; SheetTotal: 10; PageSetup: Record=PageOptions¦CenterHorizontal=True¦CenterVertical=True¦PrintScale=1.00¦XCorrection=1.00¦YCorrection=1.00¦PrintKind=0¦BorderSize=5000000¦LeftOffset=0¦BottomOffset=0¦Orientation=2¦PaperLength=1000¦PaperWidth=1000¦Scale=100¦PaperSource=15¦PrintQuality=600¦MediaType=1¦DitherType=10¦PaperKind=Letter¦PrintScaleMode=1
Used 4 times, as channels U_TIDA-00764_Signal_Chain/Channel_Inputs/NoCMCh1, U_TIDA-00764_Signal_Chain/Channel_Inputs/NoCMCh2, U_TIDA-00764_Signal_Chain/Channel_Inputs/NoCMCh3, U_TIDA-00764_Signal_Chain/Channel_Inputs/NoCMCh4. Parts and nets are listed once, with the designators drawn on the sheet.
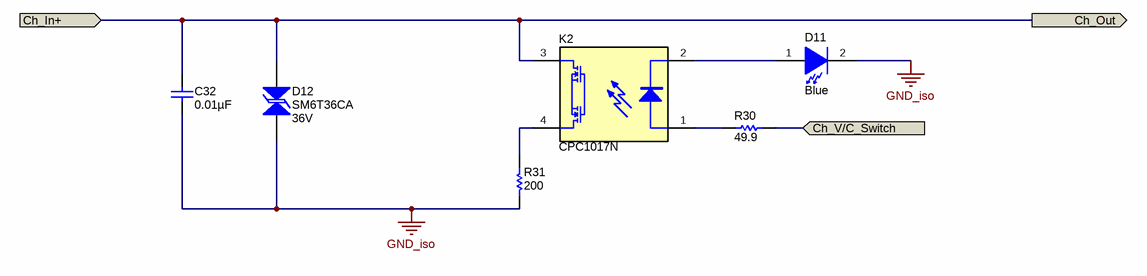
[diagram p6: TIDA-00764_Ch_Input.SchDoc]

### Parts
C32  ValueDisplayed: 0.01µF  [0603]  (hidden comment: C1608X7R2A103K)
D11  value Blue  [LB Q39G_BLUE]  (hidden comment: LB Q39G-L2N2-35-1)
D12  SM6T36CA  value 36V  [SMB-Bi]
K2  CPC1017N  [RELAY_CPC1017N]
R30  ValueDisplayed: 49.9  [0603]  (hidden comment: CRCW060349R9FKEA)
R31  ValueDisplayed: 200  [0805_HV]  (hidden comment: RT0805BRD07200RL)

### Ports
Ch_In+ (in), Ch_Out (out), Ch_V/C_Switch (in)

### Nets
GND_iso: C32.2 D11.2(K) D12.1 R31.1
Ch_In+: C32.1 D12.2 K2.3(LOAD) ; port Ch_Out, port Ch_In+
Ch_V/C_Switch: R30.2 ; port Ch_V/C_Switch
NetD11_1: D11.1(A) K2.2(CONTROL)
NetK2_1: K2.1(CONTROL+) R30.1
NetK2_4: K2.4(LOAD) R31.2

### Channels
U_TIDA-00764_Signal_Chain/Channel_Inputs/NoCMCh1: designators end in _NoCMCh1; ports Ch_In+=Ch_In+ Ch_Out=Ch_In+ Ch_V/C_Switch=Ch_V/C_Switch
U_TIDA-00764_Signal_Chain/Channel_Inputs/NoCMCh2: designators end in _NoCMCh2; ports Ch_In+=Ch_In+ Ch_Out=Ch_In+ Ch_V/C_Switch=Ch_V/C_Switch
U_TIDA-00764_Signal_Chain/Channel_Inputs/NoCMCh3: designators end in _NoCMCh3; ports Ch_In+=Ch_In+ Ch_Out=Ch_In+ Ch_V/C_Switch=Ch_V/C_Switch
U_TIDA-00764_Signal_Chain/Channel_Inputs/NoCMCh4: designators end in _NoCMCh4; ports Ch_In+=Ch_In+ Ch_Out=Ch_In+ Ch_V/C_Switch=Ch_V/C_Switch

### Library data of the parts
C32 = C1608X7R2A103K: as C28 on sheet TIDA-00764_CMCh_Input
D11 = LB Q39G-L2N2-35-1: as D8 on sheet TIDA-00764_CMCh_Input
D12 = SM6T36CA: as D9 on sheet TIDA-00764_CMCh_Input
K2 = CPC1017N: as K1 on sheet TIDA-00764_CMCh_Input
R30 = CRCW060349R9FKEA: as R28 on sheet TIDA-00764_CMCh_Input
R31 = RT0805BRD07200RL: RES, 200, 0.1%, 0.125 W, 0805; Manufacturer: Yageo America; CompType: Resistor; Value: 200; Value_Code: 200R; Tolerance_%: 0.1; Power_W: 0.125; Value2: 0.125W; VDC_V: 150; TempCo: 25 ppm/C; EIA_Code: E192; U/M: EA; AEC Category: Q200

## Sheet TIDA-00764_MUX_Stage.SchDoc: MUX Stage
size 431 x 279 mm; Date: Not shown in title block; ApprovedBy: Not shown in title block; CheckedBy: Not shown in title block; Author: Not shown in title block; CompanyName: Not shown in title block; DrawnBy: Tobias Puetz; Engineer: Not shown in title block; Organization: Not shown in title block; Address1: Not shown in title block; Address2: Not shown in title block; Address3: Not shown in title block; Address4: Not shown in title block; DocumentNumber: 10; Revision: Use project parameter SCH_Rev; SheetNumber: 10; SheetTotal: 10; PageSetup: Record=PageOptions¦CenterHorizontal=True¦CenterVertical=True¦PrintScale=1.00¦XCorrection=1.00¦YCorrection=1.00¦PrintKind=0¦BorderSize=5000000¦LeftOffset=0¦BottomOffset=0¦Orientation=2¦PaperLength=1000¦PaperWidth=1000¦Scale=100¦PaperSource=15¦PrintQuality=600¦MediaType=1¦DitherType=10¦PaperKind=Letter¦PrintScaleMode=1
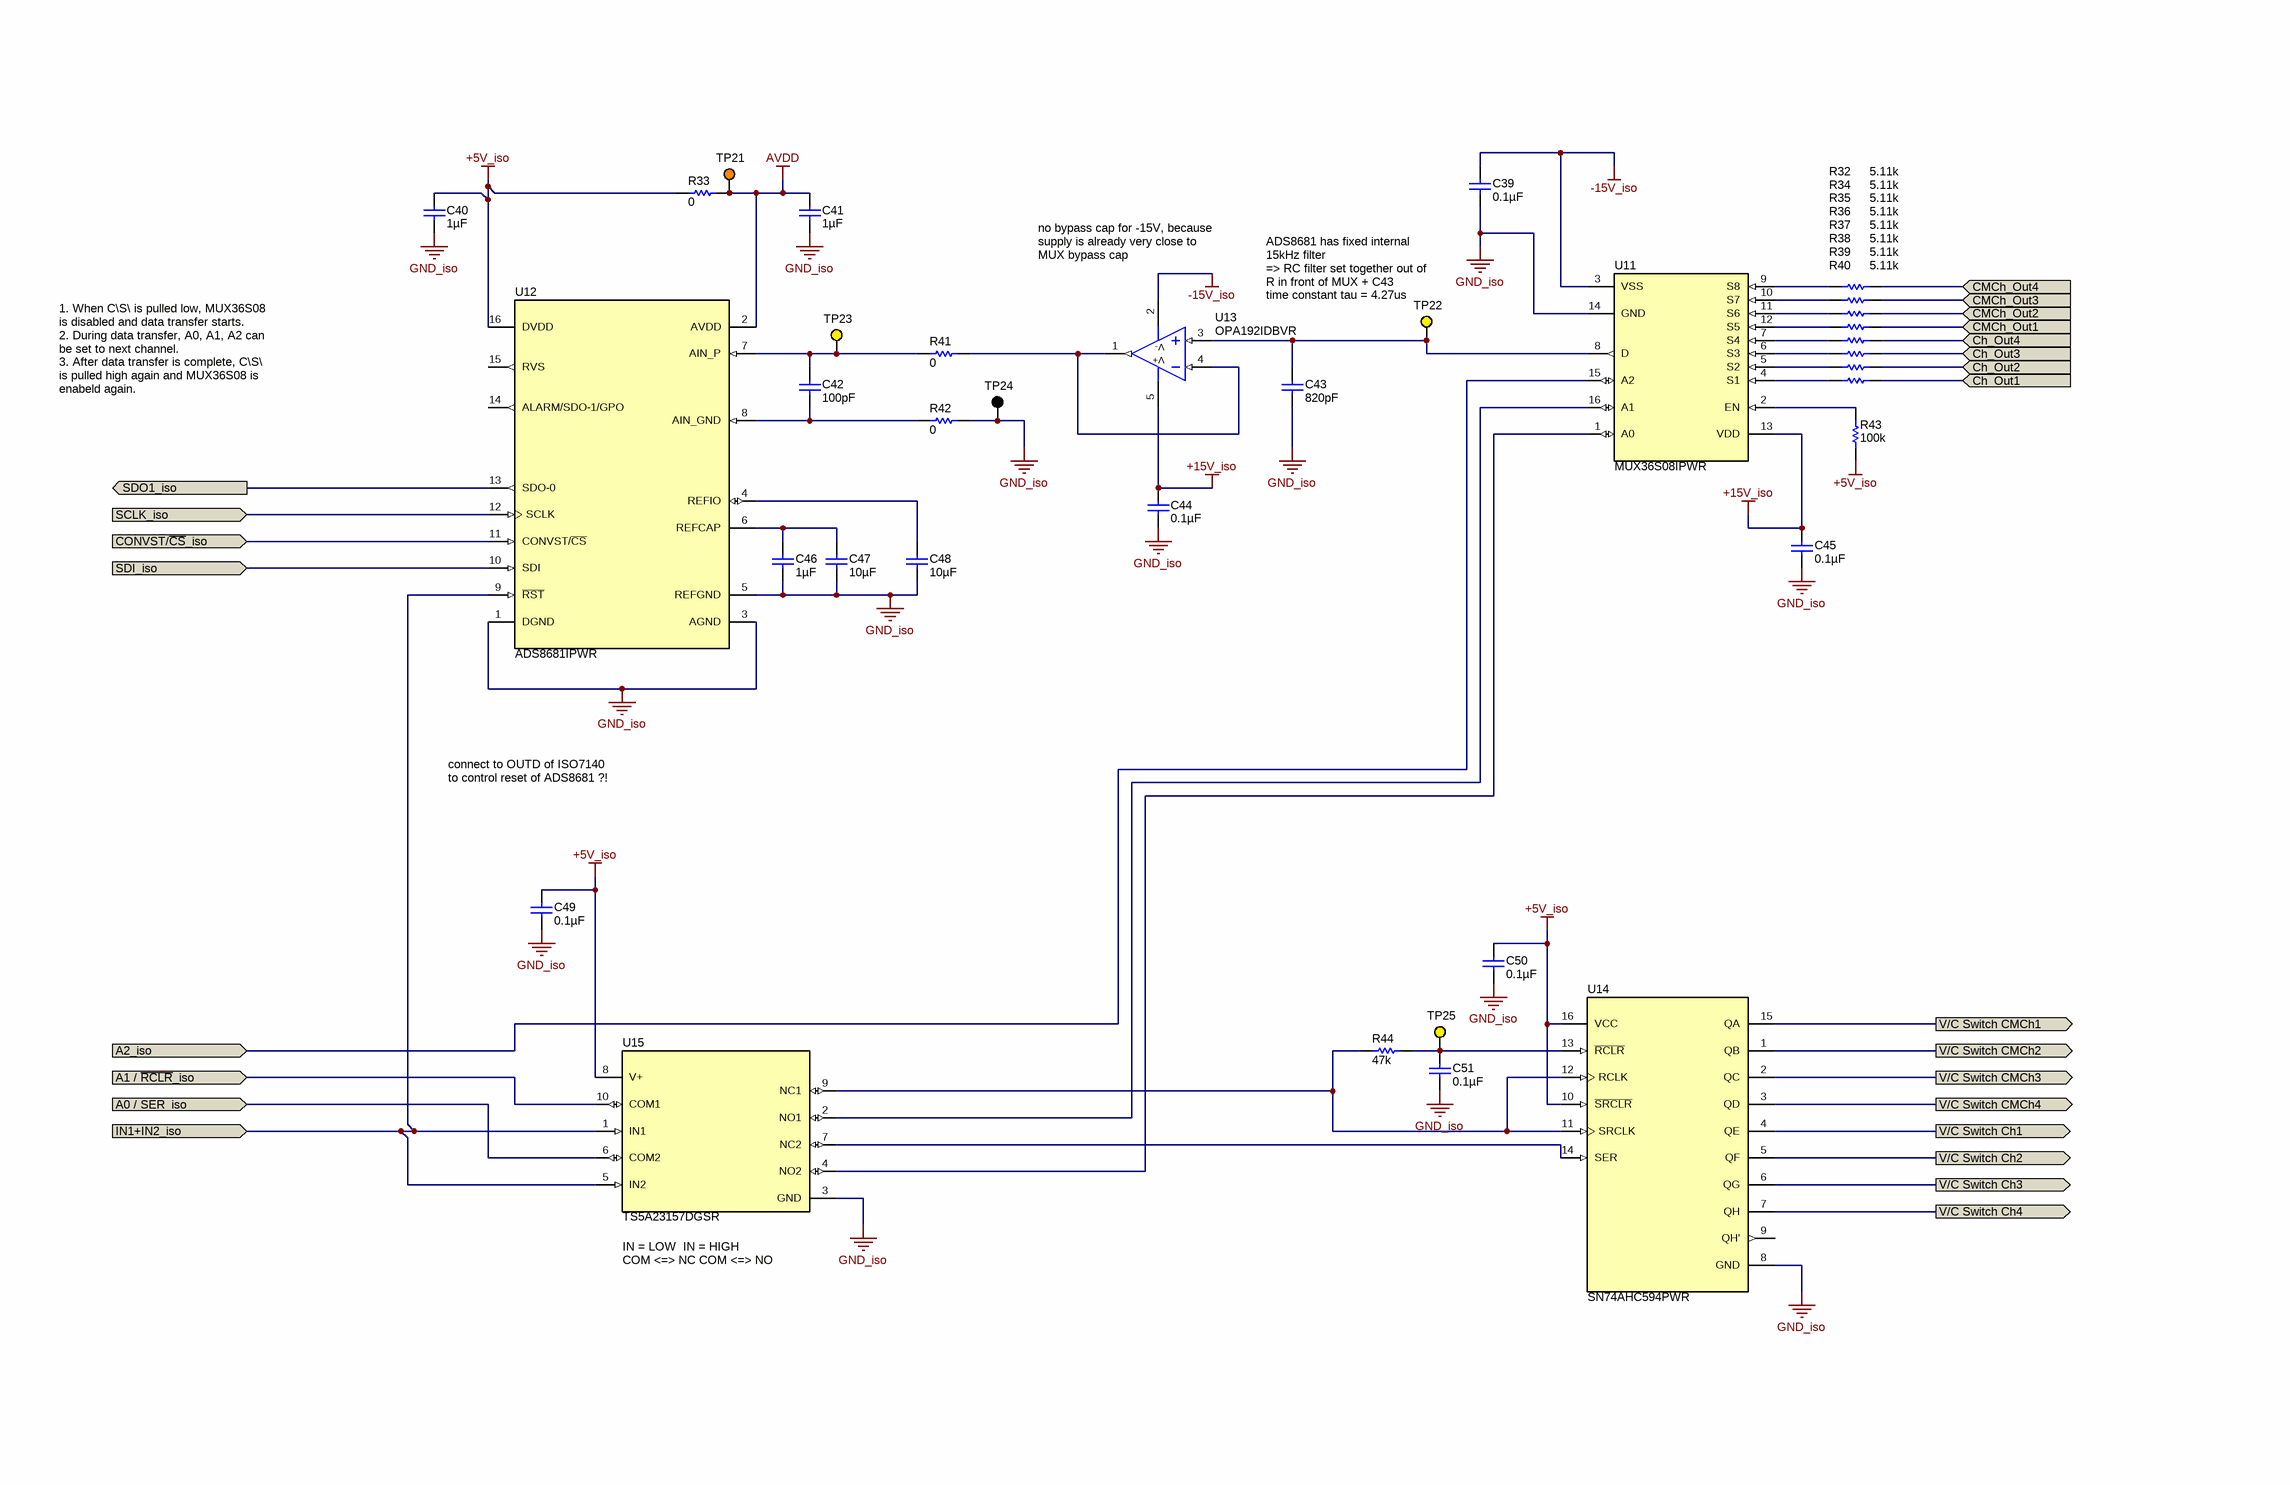
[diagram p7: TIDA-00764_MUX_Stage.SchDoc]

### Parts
C39  ValueDisplayed: 0.1µF  [0603]  (hidden comment: C1608X7R1H104K)
C40  ValueDisplayed: 1µF  [0603]  (hidden comment: C1608X7R1C105K080AC)
C41  ValueDisplayed: 1µF  [0603]  (hidden comment: C1608X7R1C105K080AC)
C42  ValueDisplayed: 100pF  [0603]  (hidden comment: C1608C0G1H101J)
C43  ValueDisplayed: 820pF  [0603]  (hidden comment: C1608C0G1H821J)
C44  ValueDisplayed: 0.1µF  [0603]  (hidden comment: C1608X7R1H104K)
C45  ValueDisplayed: 0.1µF  [0603]  (hidden comment: C1608X7R1H104K)
C46  ValueDisplayed: 1µF  [0603]  (hidden comment: C1608X7R1C105K080AC)
C47  ValueDisplayed: 10µF  [0805_HV]  (hidden comment: C2012X7R1A106K125AC)
C48  ValueDisplayed: 10µF  [0805_HV]  (hidden comment: C2012X7R1A106K125AC)
C49  ValueDisplayed: 0.1µF  [0603]  (hidden comment: C1608X7R1C104K)
C50  ValueDisplayed: 0.1µF  [0603]  (hidden comment: C1608X7R1C104K)
C51  ValueDisplayed: 0.1µF  [0603]  (hidden comment: C1608X7R1C104K)
R32  ValueDisplayed: 5.11k  [0603]  (hidden comment: CRCW06035K11FKEA)
R33  ValueDisplayed: 0  [0603]  (hidden comment: CRCW06030000Z0EA)
R34  ValueDisplayed: 5.11k  [0603]  (hidden comment: CRCW06035K11FKEA)
R35  ValueDisplayed: 5.11k  [0603]  (hidden comment: CRCW06035K11FKEA)
R36  ValueDisplayed: 5.11k  [0603]  (hidden comment: CRCW06035K11FKEA)
R37  ValueDisplayed: 5.11k  [0603]  (hidden comment: CRCW06035K11FKEA)
R38  ValueDisplayed: 5.11k  [0603]  (hidden comment: CRCW06035K11FKEA)
R39  ValueDisplayed: 5.11k  [0603]  (hidden comment: CRCW06035K11FKEA)
R40  ValueDisplayed: 5.11k  [0603]  (hidden comment: CRCW06035K11FKEA)
R41  ValueDisplayed: 0  [0603]  (hidden comment: CRCW06030000Z0EA)
R42  ValueDisplayed: 0  [0603]  (hidden comment: CRCW06030000Z0EA)
R43  ValueDisplayed: 100k  [0603]  (hidden comment: CRCW0603100KJNEA)
R44  ValueDisplayed: 47k  [0603]  (hidden comment: CRCW060347K0JNEA)
TP21  5003  [Keystone5003]  (value not drawn)
TP22  5004  [Keystone5004]  (value not drawn)
TP23  5004  [Keystone5004]  (value not drawn)
TP24  5001  [Keystone5001]  (value not drawn)
TP25  5004  [Keystone5004]  (value not drawn)
U11  MUX36S08IPWR  [PW0016A_N]
U12  ADS8681IPWR  [PW0016A_N]
U13  OPA192IDBVR  [DBV0005A_N]
U14  SN74AHC594PWR  [PW0016A_N]
U15  TS5A23157DGSR  [DGS0010A_N]

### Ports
A0 / SER_iso (in), A1 / ~{RCLR}_iso (in), A2_iso (in), Ch_Out1 (in), Ch_Out2 (in), Ch_Out3 (in), Ch_Out4 (in), CMCh_Out1 (in), CMCh_Out2 (in), CMCh_Out3 (in), CMCh_Out4 (in), CONVST/~{CS}_iso (in), IN1+IN2_iso (in), SCLK_iso (in), SDI_iso (in), SDO1_iso (out), V/C Switch Ch1 (out), V/C Switch Ch2 (out), V/C Switch Ch3 (out), V/C Switch Ch4 (out), V/C Switch CMCh1 (out), V/C Switch CMCh2 (out), V/C Switch CMCh3 (out), V/C Switch CMCh4 (out)

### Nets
+5V_iso: C40.1 C49.1 C50.1 R33.1 R43.2 U12.16(DVDD) U14.10(~{SRCLR}) U14.16(VCC) U15.8(V+)
+15V_iso: C44.1 C45.2 U11.13(VDD) U13.5(V+)
-15V_iso: C39.2 U11.3(VSS) U13.2(V-)
AVDD: C41.1 R33.2 TP21.1 U12.2(AVDD)
GND_iso: C39.1 C40.2 C41.2 C43.2 C44.2 C45.1 C46.2 C47.1 C48.1 C49.2 C50.2 C51.2 R42.2 TP24.1 U11.14(GND) U12.1(DGND) U12.3(AGND) U12.5(REFGND) U14.8(GND) U15.3(GND)
A0 / SER_iso: U15.6(COM2) ; port A0 / SER_iso
A1 / ~{RCLR}_iso: U15.10(COM1) ; port A1 / ~{RCLR}_iso
A2_iso: U11.15(A2) ; port A2_iso
Ch_In+: R37.2 ; port Ch_Out4
Ch_In+: R38.2 ; port Ch_Out3  [a separate net that carries the same name]
Ch_In+: R39.2 ; port Ch_Out2  [a separate net that carries the same name]
Ch_In+: R40.2 ; port Ch_Out1  [a separate net that carries the same name]
Ch_V/C_Switch: U14.4(QE) ; port V/C Switch Ch1
Ch_V/C_Switch: U14.5(QF) ; port V/C Switch Ch2  [a separate net that carries the same name]
Ch_V/C_Switch: U14.6(QG) ; port V/C Switch Ch3  [a separate net that carries the same name]
Ch_V/C_Switch: U14.7(QH) ; port V/C Switch Ch4  [a separate net that carries the same name]
CMCh_Out: R36.2 ; port CMCh_Out1
CMCh_Out: R34.2 ; port CMCh_Out3  [a separate net that carries the same name]
CMCh_Out: R35.2 ; port CMCh_Out2  [a separate net that carries the same name]
CMCh_Out: R32.2 ; port CMCh_Out4  [a separate net that carries the same name]
CMCh_V/C_Switch: U14.15(QA) ; port V/C Switch CMCh1
CMCh_V/C_Switch: U14.2(QC) ; port V/C Switch CMCh3  [a separate net that carries the same name]
CMCh_V/C_Switch: U14.1(QB) ; port V/C Switch CMCh2  [a separate net that carries the same name]
CMCh_V/C_Switch: U14.3(QD) ; port V/C Switch CMCh4  [a separate net that carries the same name]
CONVST/~{CS}_iso: U12.11(CONVST/~{CS}) ; port CONVST/~{CS}_iso
IN1+IN2_iso: U12.9(~{RST}) U15.1(IN1) U15.5(IN2) ; port IN1+IN2_iso
SCLK_iso: U12.12(SCLK) ; port SCLK_iso
SDI_iso: U12.10(SDI) ; port SDI_iso
SDO1_iso: U12.13(SDO-0) ; port SDO1_iso
NetC42_1: C42.1 R41.1 TP23.1 U12.7(AIN_P)
NetC42_2: C42.2 R42.1 U12.8(AIN_GND)
NetC43_1: C43.1 TP22.1 U11.8(D) U13.3(IN+)
NetC46_1: C46.1 C47.2 U12.6(REFCAP)
NetC48_2: C48.2 U12.4(REFIO)
NetC51_1: C51.1 R44.2 TP25.1 U14.13(~{RCLR})
NetR32_1: R32.1 U11.9(S8)
NetR34_1: R34.1 U11.10(S7)
NetR35_1: R35.1 U11.11(S6)
NetR36_1: R36.1 U11.12(S5)
NetR37_1: R37.1 U11.7(S4)
NetR38_1: R38.1 U11.6(S3)
NetR39_1: R39.1 U11.5(S2)
NetR40_1: R40.1 U11.4(S1)
NetR41_2: R41.2 U13.1(OUT) U13.4(IN-)
NetR43_1: R43.1 U11.2(EN)
NetR44_1: R44.1 U14.11(SRCLK) U14.12(RCLK) U15.9(NC1)
NetU11_1: U11.1(A0) U15.4(NO2)
NetU11_16: U11.16(A1) U15.2(NO1)
NetU14_14: U14.14(SER) U15.7(NC2)

Not connected (* = marked no-connect by the designer): U12 14(ALARM/SDO-1/GPO) 15(RVS); U14 9(QH')

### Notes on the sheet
- no bypass cap for -15V, because supply is already very close to MUX bypass cap
- (near TP22) ADS8681 has fixed internal 15kHz filter
  => RC filter set together out of R in front of MUX + C43
  time constant tau = 4.27us
- 1. When C\S\ is pulled low, MUX36S08 is disabled and data transfer starts.
  2. During data transfer, A0, A1, A2 can be set to next channel.
  3. After data transfer is complete, C\S\ is pulled high again and MUX36S08 is enabeld again.
- connect to OUTD of ISO7140 to control reset of ADS8681 ?!
- (near U15) IN = LOW		IN = HIGH
  COM <=> NC	COM <=> NO

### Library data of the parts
C39 C44 C45 = C1608X7R1H104K: as C25 on sheet TIDA-00764_CMCh_Input
C40 C41 C46 = C1608X7R1C105K080AC: as C26 on sheet TIDA-00764_CMCh_Input
C42 = C1608C0G1H101J: CAP, CERM, 100 pF, 50 V, +/- 5%, C0G/NP0, 0603; Manufacturer: TDK; Polarized: N; CompType: Capacitor; Value: 100pF; U/M: EA; Cap_F: 0.0000000001; Tolerance_%: 5; ESR_ohm: 0.1679; Value1: 0.1679 ohm; VDC_V: 50; Value2: 50V; TaMin_C: -55; TaMax_C: 125; AEC Category: Q200
C43 = C1608C0G1H821J: CAP, CERM, 820 pF, 50 V, +/- 5%, C0G/NP0, 0603; Manufacturer: TDK; Polarized: N; CompType: Capacitor; Value: 820pF; U/M: EA; Cap_F: 0.00000000082; Tolerance_%: 5; ESR_ohm: 0.0482; Value1: 0.0482 ohm; VDC_V: 50; Value2: 50V; TaMin_C: -55; TaMax_C: 125; AEC Category: Q200
C47 C48 = C2012X7R1A106K125AC: CAP, CERM, 10 µF, 10 V, +/- 10%, X7R, 0805; Manufacturer: TDK; Polarized: N; CompType: Capacitor; Value: 10uF; U/M: EA; Cap_F: 0.00001; Tolerance_%: 10; Value1: Unknown; Value2: 10V; TaMin_C: -55; TaMax_C: 125; Cap_Case: 0805; AEC Category: Q200
C49-C51 = C1608X7R1C104K: CAP, CERM, 0.1 µF, 16 V, +/- 10%, X7R, 0603; Manufacturer: TDK; Polarized: N; CompType: Capacitor; Value: 0.1uF; U/M: EA; Cap_F: 0.0000001; Tolerance_%: 10; ESR_ohm: 0.017; Value1: 0.017 ohm; VDC_V: 16; Value2: 16V; TaMin_C: -55; TaMax_C: 125; AEC Category: Q200
R32 R34-R40 = CRCW06035K11FKEA: RES, 5.11 k, 1%, 0.1 W, 0603; Manufacturer: Vishay-Dale; CompType: Resistor; Value: 5.11k; Res_ohm: 5110; Value_Code: 5k11; Tolerance_%: 1; Power_W: 0.1; Value2: 0.1W; VDC_V: 75; TempCo: 100 ppm/C; EIA_Code: E96; U/M: EA; AEC Category: Q200
R33 R41 R42 = CRCW06030000Z0EA: as R5 on sheet TIDA-00764_Cape
R43 = CRCW0603100KJNEA: RES, 100 k, 5%, 0.1 W, 0603; Manufacturer: Vishay-Dale; CompType: Resistor; Value: 100k; Res_ohm: 100000; Tolerance_%: 5; Power_W: 0.1; Value2: 0.1W; VDC_V: 75; TempCo: 200 ppm/C; EIA_Code: E24; U/M: EA; AEC Category: Q200
R44 = CRCW060347K0JNEA: RES, 47 k, 5%, 0.1 W, 0603; Manufacturer: Vishay-Dale; CompType: Resistor; Value: 47k; Res_ohm: 47000; Value_Code: 47k0; Tolerance_%: 5; Power_W: 0.1; Value2: 0.1W; VDC_V: 75; TempCo: 200 ppm/C; EIA_Code: E24; U/M: EA; AEC Category: Q200
TP21 = 5003: Test Point, Miniature, Orange, TH; Manufacturer: Keystone; CompType: Test Point Loop; ContactFinish: Silver
TP22 TP23 TP25 = 5004: Test Point, Miniature, Yellow, TH; Manufacturer: Keystone; CompType: Test Point Loop; ContactFinish: Silver
TP24 = 5001: as TP10 on sheet TIDA-00764_Signal_Chain
U11 = MUX36S08IPWR: Fault-Protected, 8-Channel, Single-Ended Multiplexer, PW0016A; Manufacturer: Texas Instruments; SymbolCreator: Altium; CompType: IC; U/M: EA
U12 = ADS8681IPWR: SAR ADC with 16 Bits, Single Channel, 1MSPS, and Bipolar Inputs off +5 V Supply, PW0016A; Manufacturer: Texas Instruments; SymbolCreator: Altium; CompType: IC; U/M: EA
U13 = OPA192IDBVR: 36-V, Precision, Rail-to-Rail Input/Output, Low Offset Voltage, Low Input Bias Current Op Amp with e-trim, DBV0005A; Alternate PartNumber: OPA192IDBVT; Manufacturer: Texas Instruments; SizeX_mm: 2.8; SizeY_mm: 2.9; SizeZ_mm: 1.45; CompType: IC; U/M: EA
U14 = SN74AHC594PWR: 8-Bit Shift Register With Output Registers, PW0016A; Manufacturer: Texas Instruments; SymbolCreator: Altium; CompType: IC; U/M: EA
U15 = TS5A23157DGSR: DUAL 10-Ohm SPDT ANALOG SWITCH, DGS0010A; Alternate PartNumber: TS5A23157DGST; Manufacturer: Texas Instruments; SymbolCreator: Altium; CompType: IC; U/M: EA

## Sheet TIDA-00764_Digital_Isolation.SchDoc: Digital Isolation
size 431 x 279 mm; Date: Not shown in title block; ApprovedBy: Not shown in title block; CheckedBy: Not shown in title block; Author: Not shown in title block; CompanyName: Not shown in title block; DrawnBy: Tobias Puetz; Engineer: Not shown in title block; Organization: Not shown in title block; Address1: Not shown in title block; Address2: Not shown in title block; Address3: Not shown in title block; Address4: Not shown in title block; DocumentNumber: 9; Revision: Use project parameter SCH_Rev; SheetNumber: 9; SheetTotal: 10; PageSetup: Record=PageOptions¦CenterHorizontal=True¦CenterVertical=True¦PrintScale=1.00¦XCorrection=1.00¦YCorrection=1.00¦PrintKind=0¦BorderSize=5000000¦LeftOffset=0¦BottomOffset=0¦Orientation=2¦PaperLength=1000¦PaperWidth=1000¦Scale=100¦PaperSource=15¦PrintQuality=600¦MediaType=1¦DitherType=10¦PaperKind=Letter¦PrintScaleMode=1
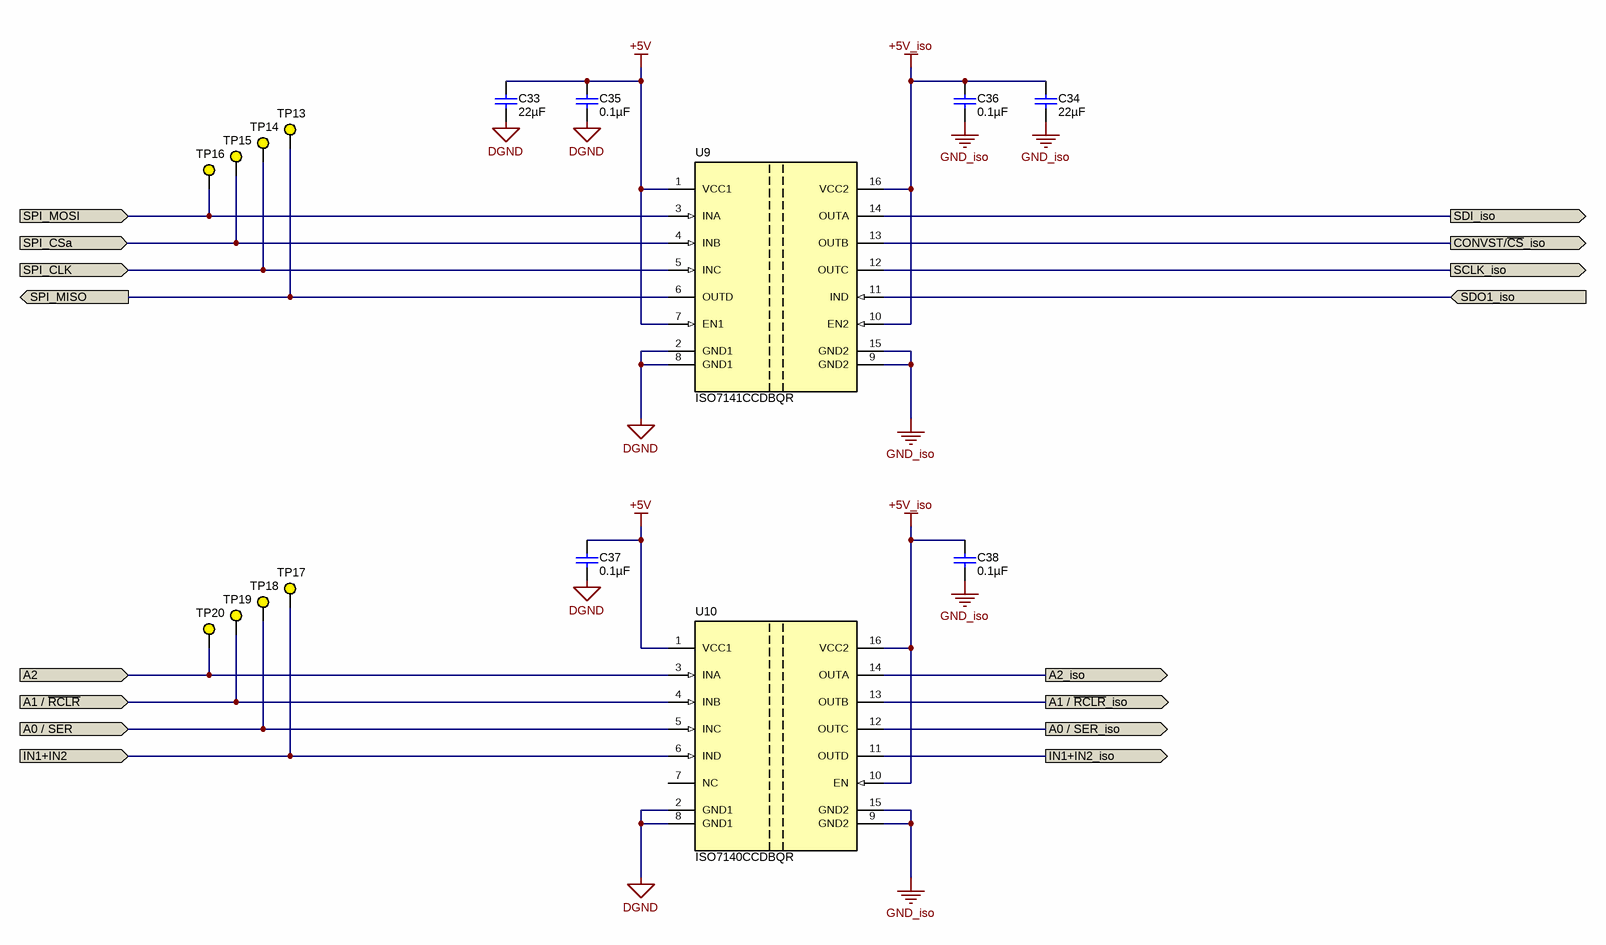
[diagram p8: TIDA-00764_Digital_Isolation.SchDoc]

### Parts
C33  ValueDisplayed: 22µF  [1206_180]  (hidden comment: GRM31CR71A226KE15L)
C34  ValueDisplayed: 22µF  [1206_180]  (hidden comment: GRM31CR71A226KE15L)
C35  ValueDisplayed: 0.1µF  [0603]  (hidden comment: C1608X7R1C104K)
C36  ValueDisplayed: 0.1µF  [0603]  (hidden comment: C1608X7R1C104K)
C37  ValueDisplayed: 0.1µF  [0603]  (hidden comment: C1608X7R1C104K)
C38  ValueDisplayed: 0.1µF  [0603]  (hidden comment: C1608X7R1C104K)
TP13  5004  [Keystone5004]  (value not drawn)
TP14  5004  [Keystone5004]  (value not drawn)
TP15  5004  [Keystone5004]  (value not drawn)
TP16  5004  [Keystone5004]  (value not drawn)
TP17  5004  [Keystone5004]  (value not drawn)
TP18  5004  [Keystone5004]  (value not drawn)
TP19  5004  [Keystone5004]  (value not drawn)
TP20  5004  [Keystone5004]  (value not drawn)
U9  ISO7141CCDBQR  [DBQ0016A_N]
U10  ISO7140CCDBQR  [DBQ0016A_N]

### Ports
A0 / SER (in), A0 / SER_iso (out), A1 / ~{RCLR} (in), A1 / ~{RCLR}_iso (out), A2 (in), A2_iso (out), CONVST/~{CS}_iso (out), IN1+IN2 (in), IN1+IN2_iso (out), SCLK_iso (out), SDI_iso (out), SDO1_iso (in), SPI_CLK (in), SPI_CSa (in), SPI_MISO (out), SPI_MOSI (in)

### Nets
+5V: C33.1 C35.1 C37.1 U9.1(VCC1) U9.7(EN1) U10.1(VCC1)
+5V_iso: C34.1 C36.1 C38.1 U9.10(EN2) U9.16(VCC2) U10.10(EN) U10.16(VCC2)
DGND: C33.2 C35.2 C37.2 U9.2(GND1) U9.8(GND1) U10.2(GND1) U10.8(GND1)
GND_iso: C34.2 C36.2 C38.2 U9.9(GND2) U9.15(GND2) U10.9(GND2) U10.15(GND2)
A0 / SER: TP18.1 U10.5(INC) ; port A0 / SER
A0 / SER_iso: U10.12(OUTC) ; port A0 / SER_iso
A1 / ~{RCLR}: TP19.1 U10.4(INB) ; port A1 / ~{RCLR}
A1 / ~{RCLR}_iso: U10.13(OUTB) ; port A1 / ~{RCLR}_iso
A2: TP20.1 U10.3(INA) ; port A2
A2_iso: U10.14(OUTA) ; port A2_iso
CONVST/~{CS}_iso: U9.13(OUTB) ; port CONVST/~{CS}_iso
IN1+IN2: TP17.1 U10.6(IND) ; port IN1+IN2
IN1+IN2_iso: U10.11(OUTD) ; port IN1+IN2_iso
SCLK_iso: U9.12(OUTC) ; port SCLK_iso
SDI_iso: U9.14(OUTA) ; port SDI_iso
SDO1_iso: U9.11(IND) ; port SDO1_iso
SPI_CLK: TP14.1 U9.5(INC) ; port SPI_CLK
SPI_CSa: TP15.1 U9.4(INB) ; port SPI_CSa
SPI_MISO: TP13.1 U9.6(OUTD) ; port SPI_MISO
SPI_MOSI: TP16.1 U9.3(INA) ; port SPI_MOSI

Not connected (* = marked no-connect by the designer): U10 7(NC)

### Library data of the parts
C33 C34 = GRM31CR71A226KE15L: CAP, CERM, 22 µF, 10 V, +/- 10%, X7R, 1206; Manufacturer: MuRata; Polarized: N; CompType: Capacitor; Value: 22uF; U/M: EA; Cap_F: 0.000022; Tolerance_%: 10; Value1: Unknown; Value2: 10V; TaMin_C: -55; TaMax_C: 125; Cap_Case: 1206; AEC Category: Q200
C35-C38 = C1608X7R1C104K: as C49 on sheet TIDA-00764_MUX_Stage
TP13-TP20 = 5004: as TP22 on sheet TIDA-00764_MUX_Stage
U9 = ISO7141CCDBQR: 4242-VPK Small-Footprint and Low-Power Quad Channels Digital Isolators, DBQ0016A; Manufacturer: Texas Instruments; SymbolCreator: a0799628; CompType: IC; U/M: EA
U10 = ISO7140CCDBQR: 4242-VPK Small-Footprint and Low-Power Quad Channels Digital Isolators, DBQ0016A; Manufacturer: Texas Instruments; SymbolCreator: a0799628; CompType: IC; U/M: EA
